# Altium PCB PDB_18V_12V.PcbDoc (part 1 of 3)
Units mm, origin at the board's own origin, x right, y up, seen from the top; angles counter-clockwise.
Board outline 185 x 160 mm, 4 copper layers (Top Layer, Int1 (GND), Int2 (GND), Bottom Layer), stack 1.636 mm thick; 209 components, 100 nets, 653 pads, 1413 vias.
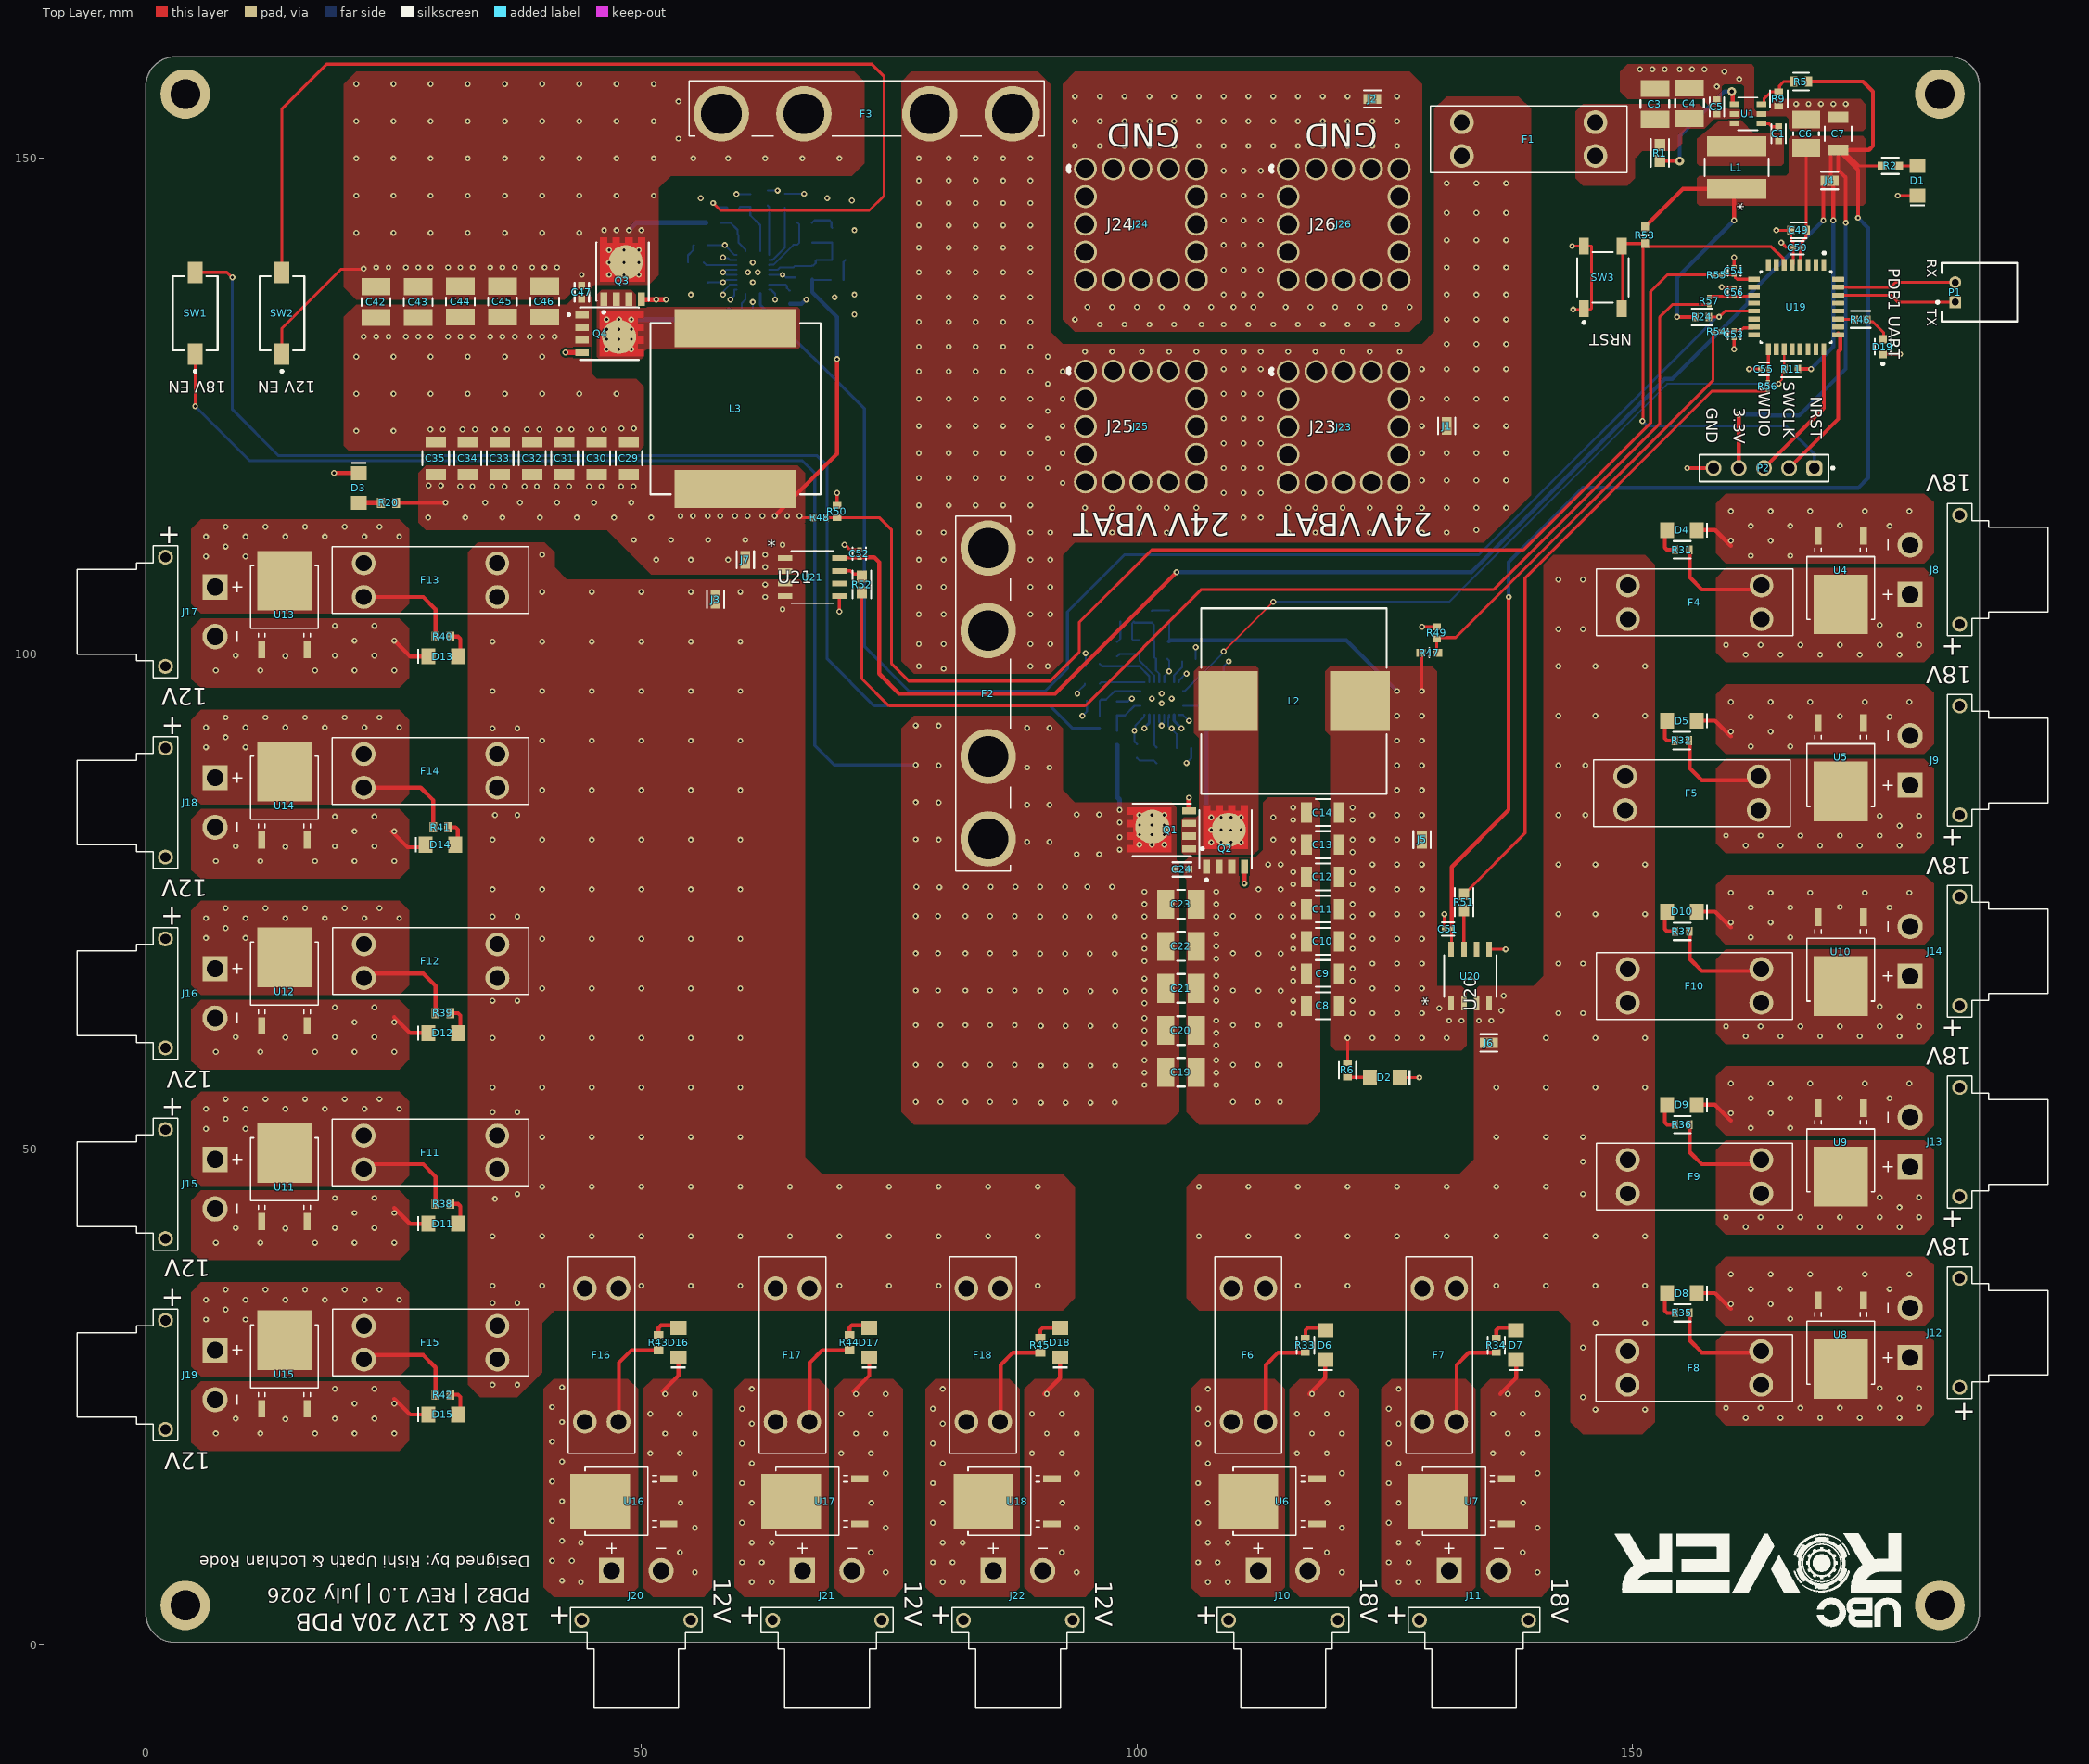
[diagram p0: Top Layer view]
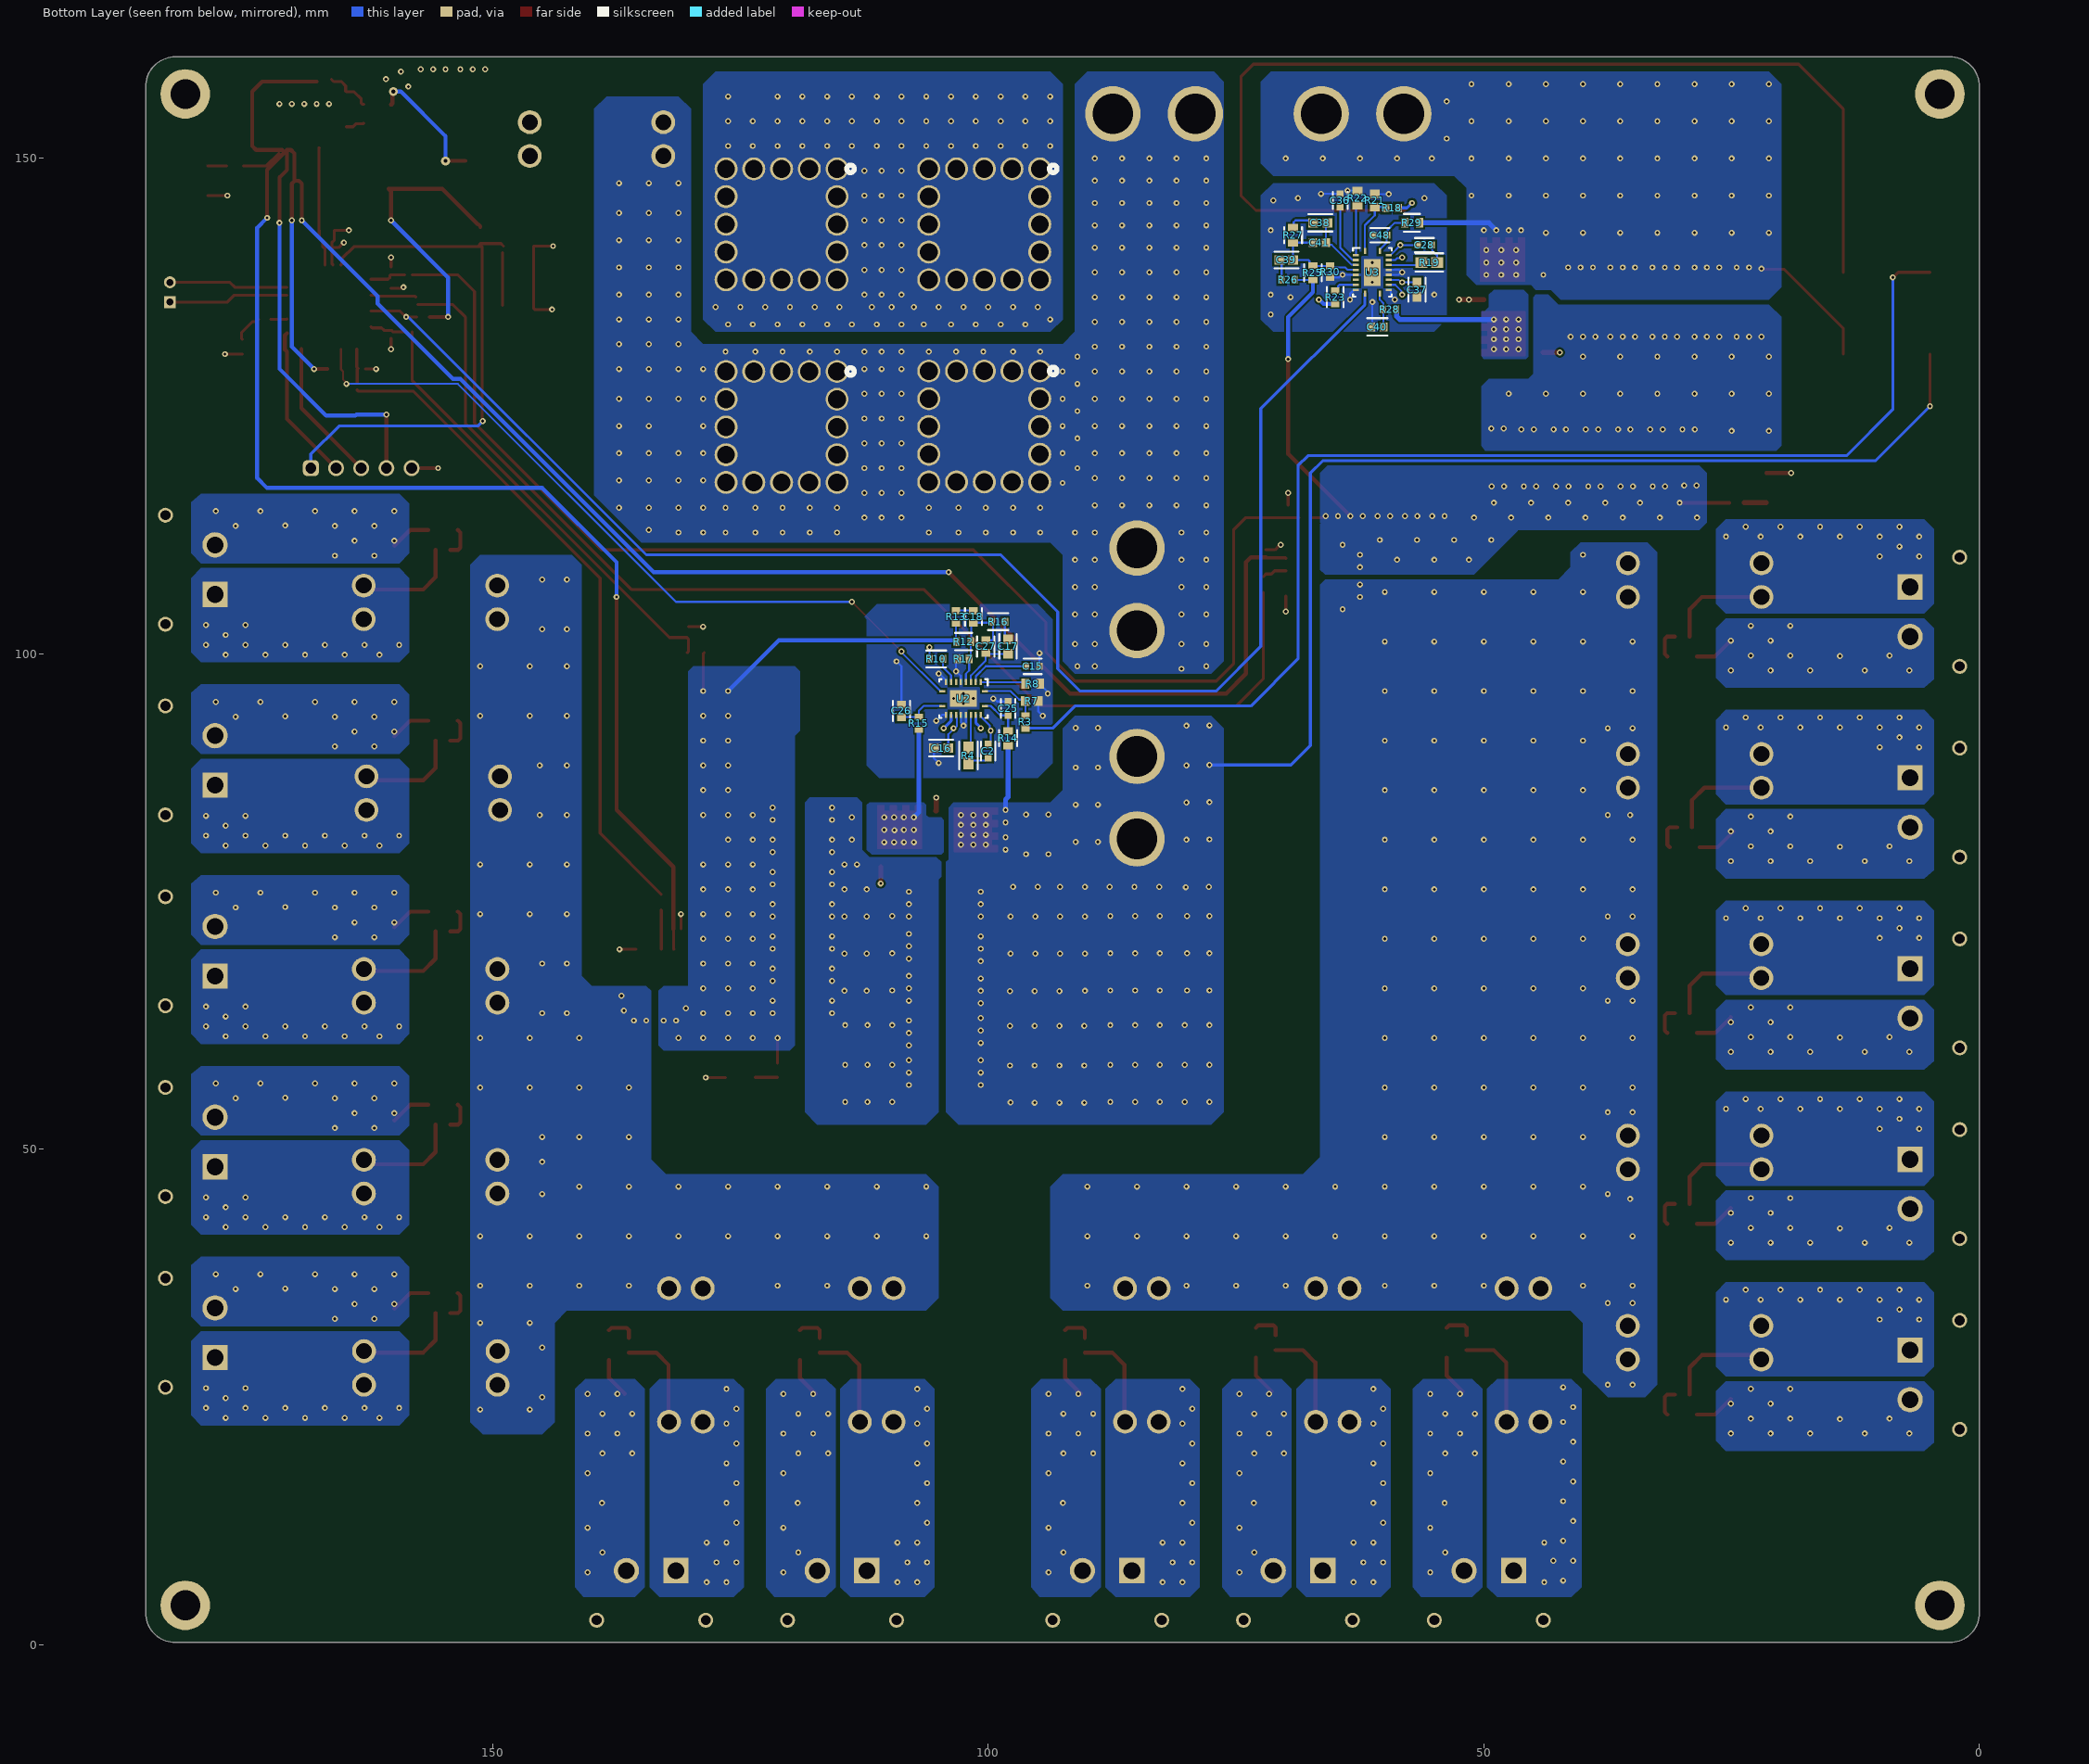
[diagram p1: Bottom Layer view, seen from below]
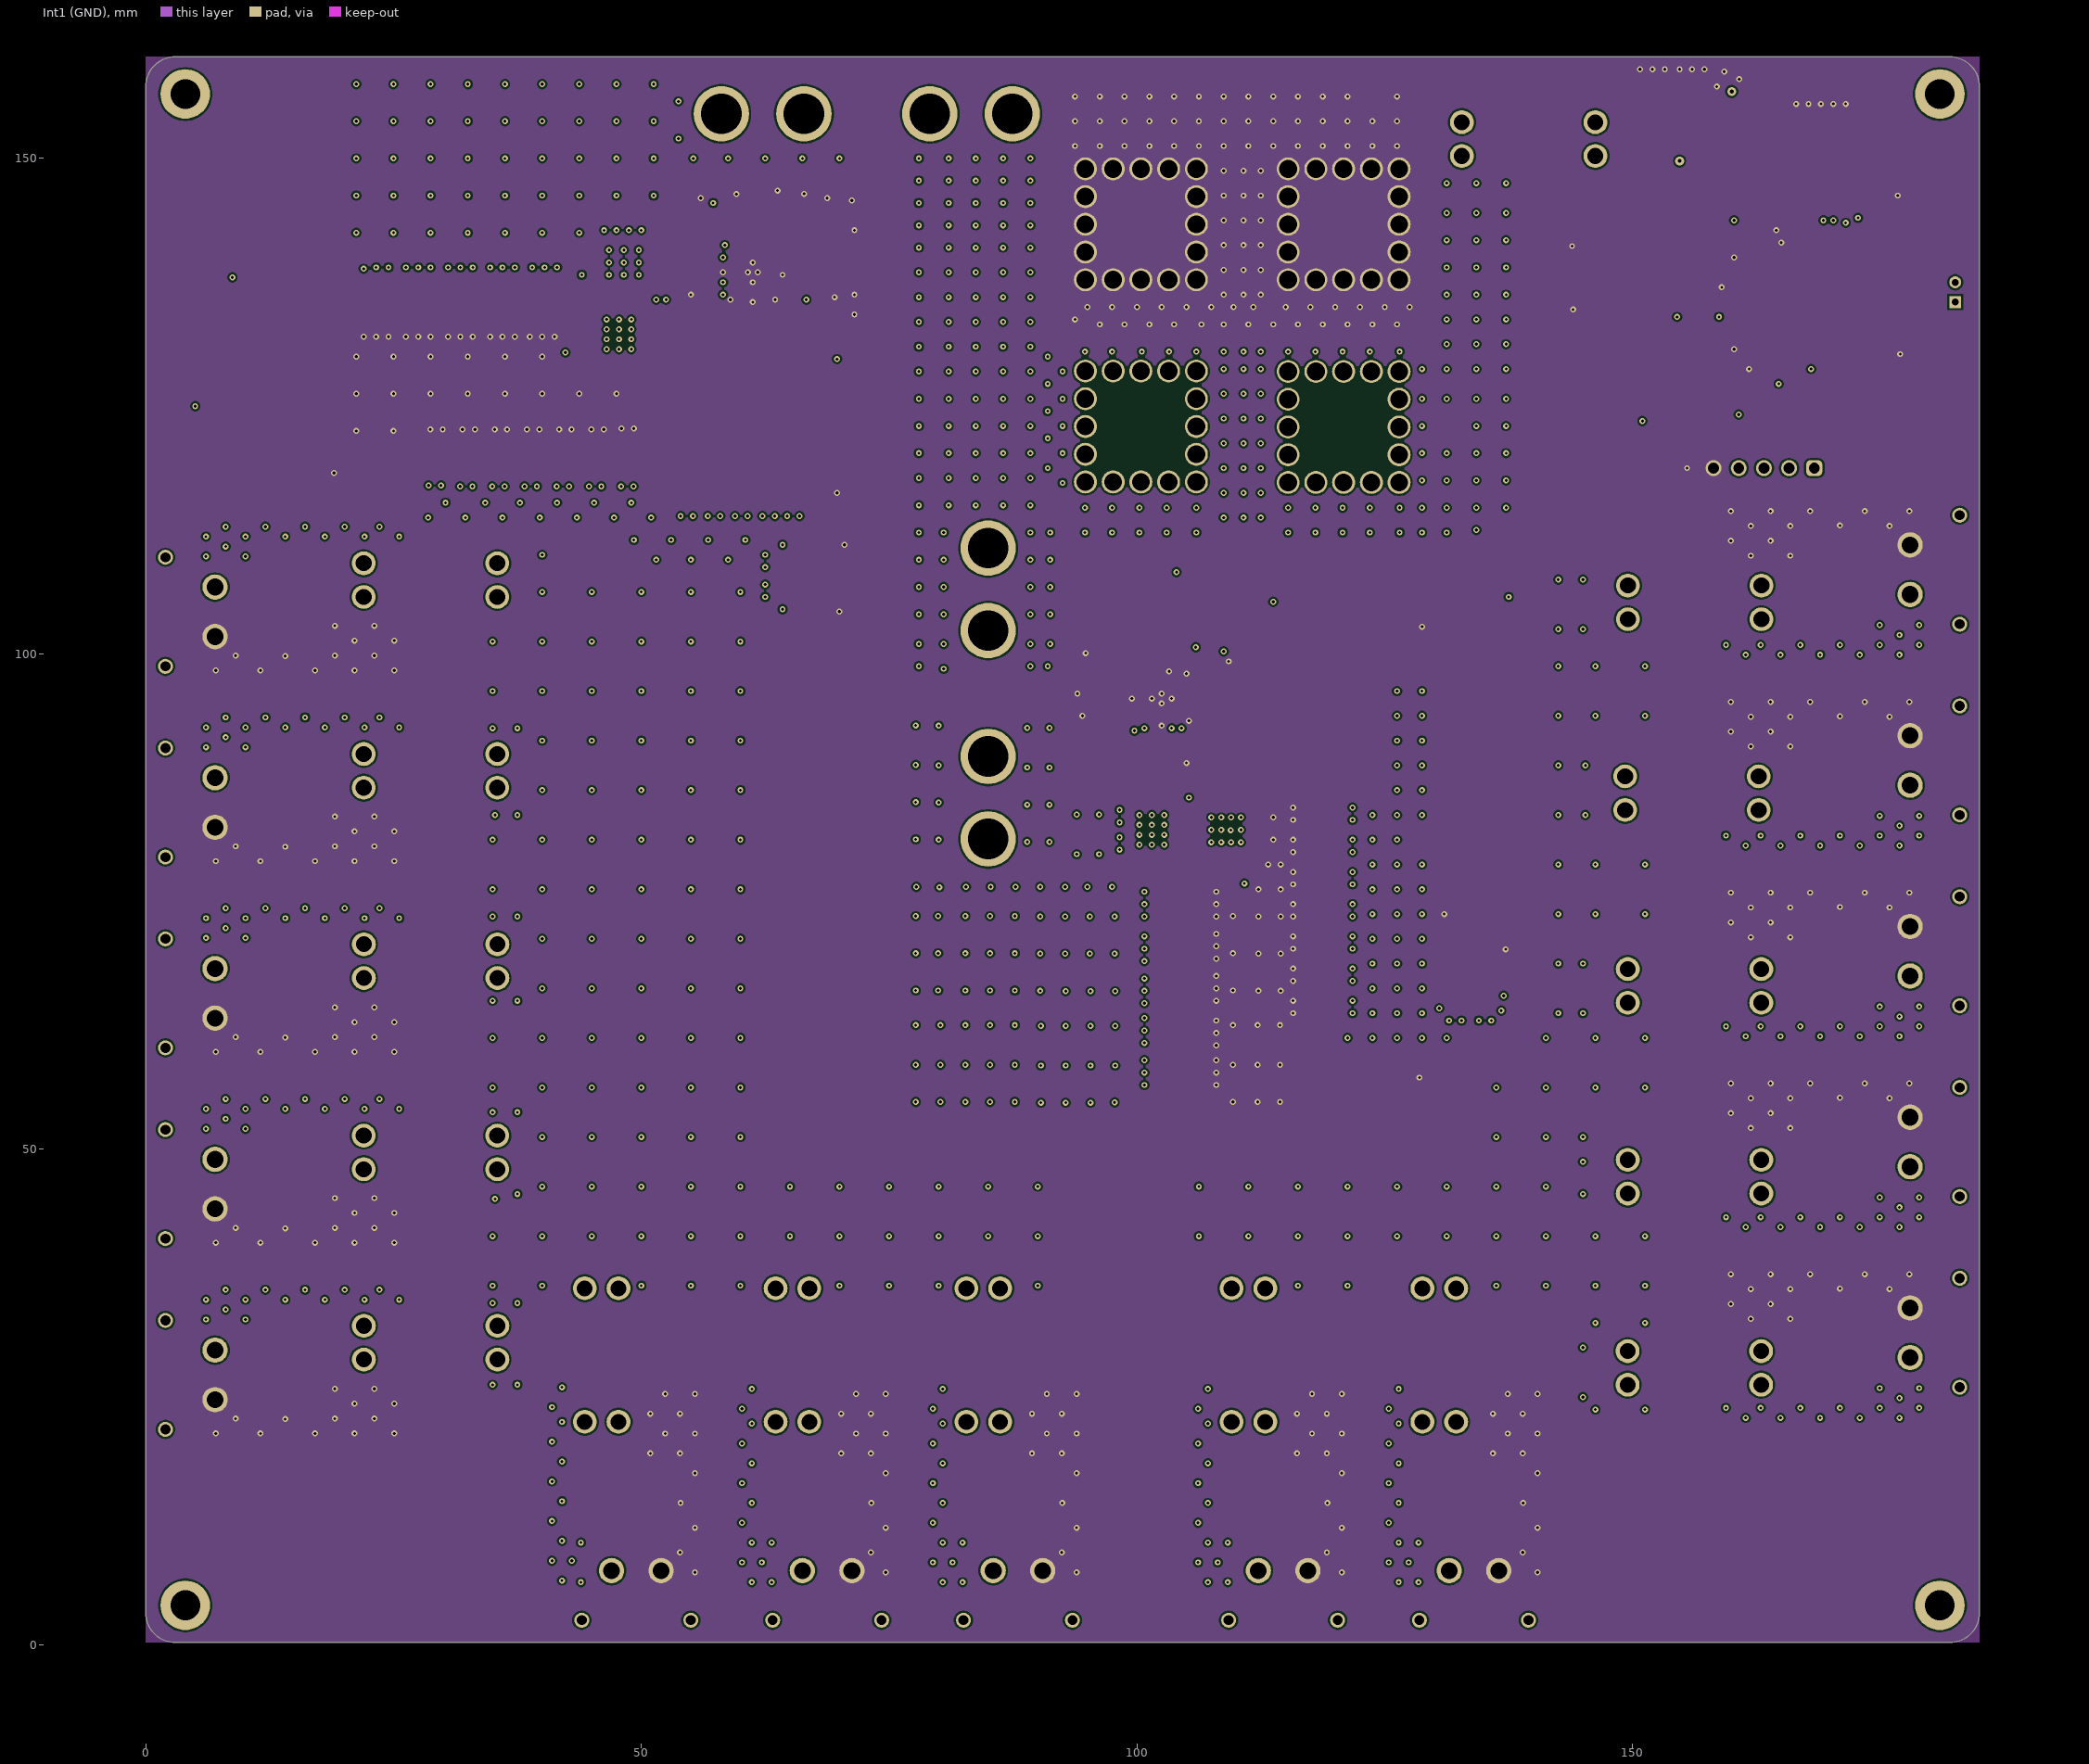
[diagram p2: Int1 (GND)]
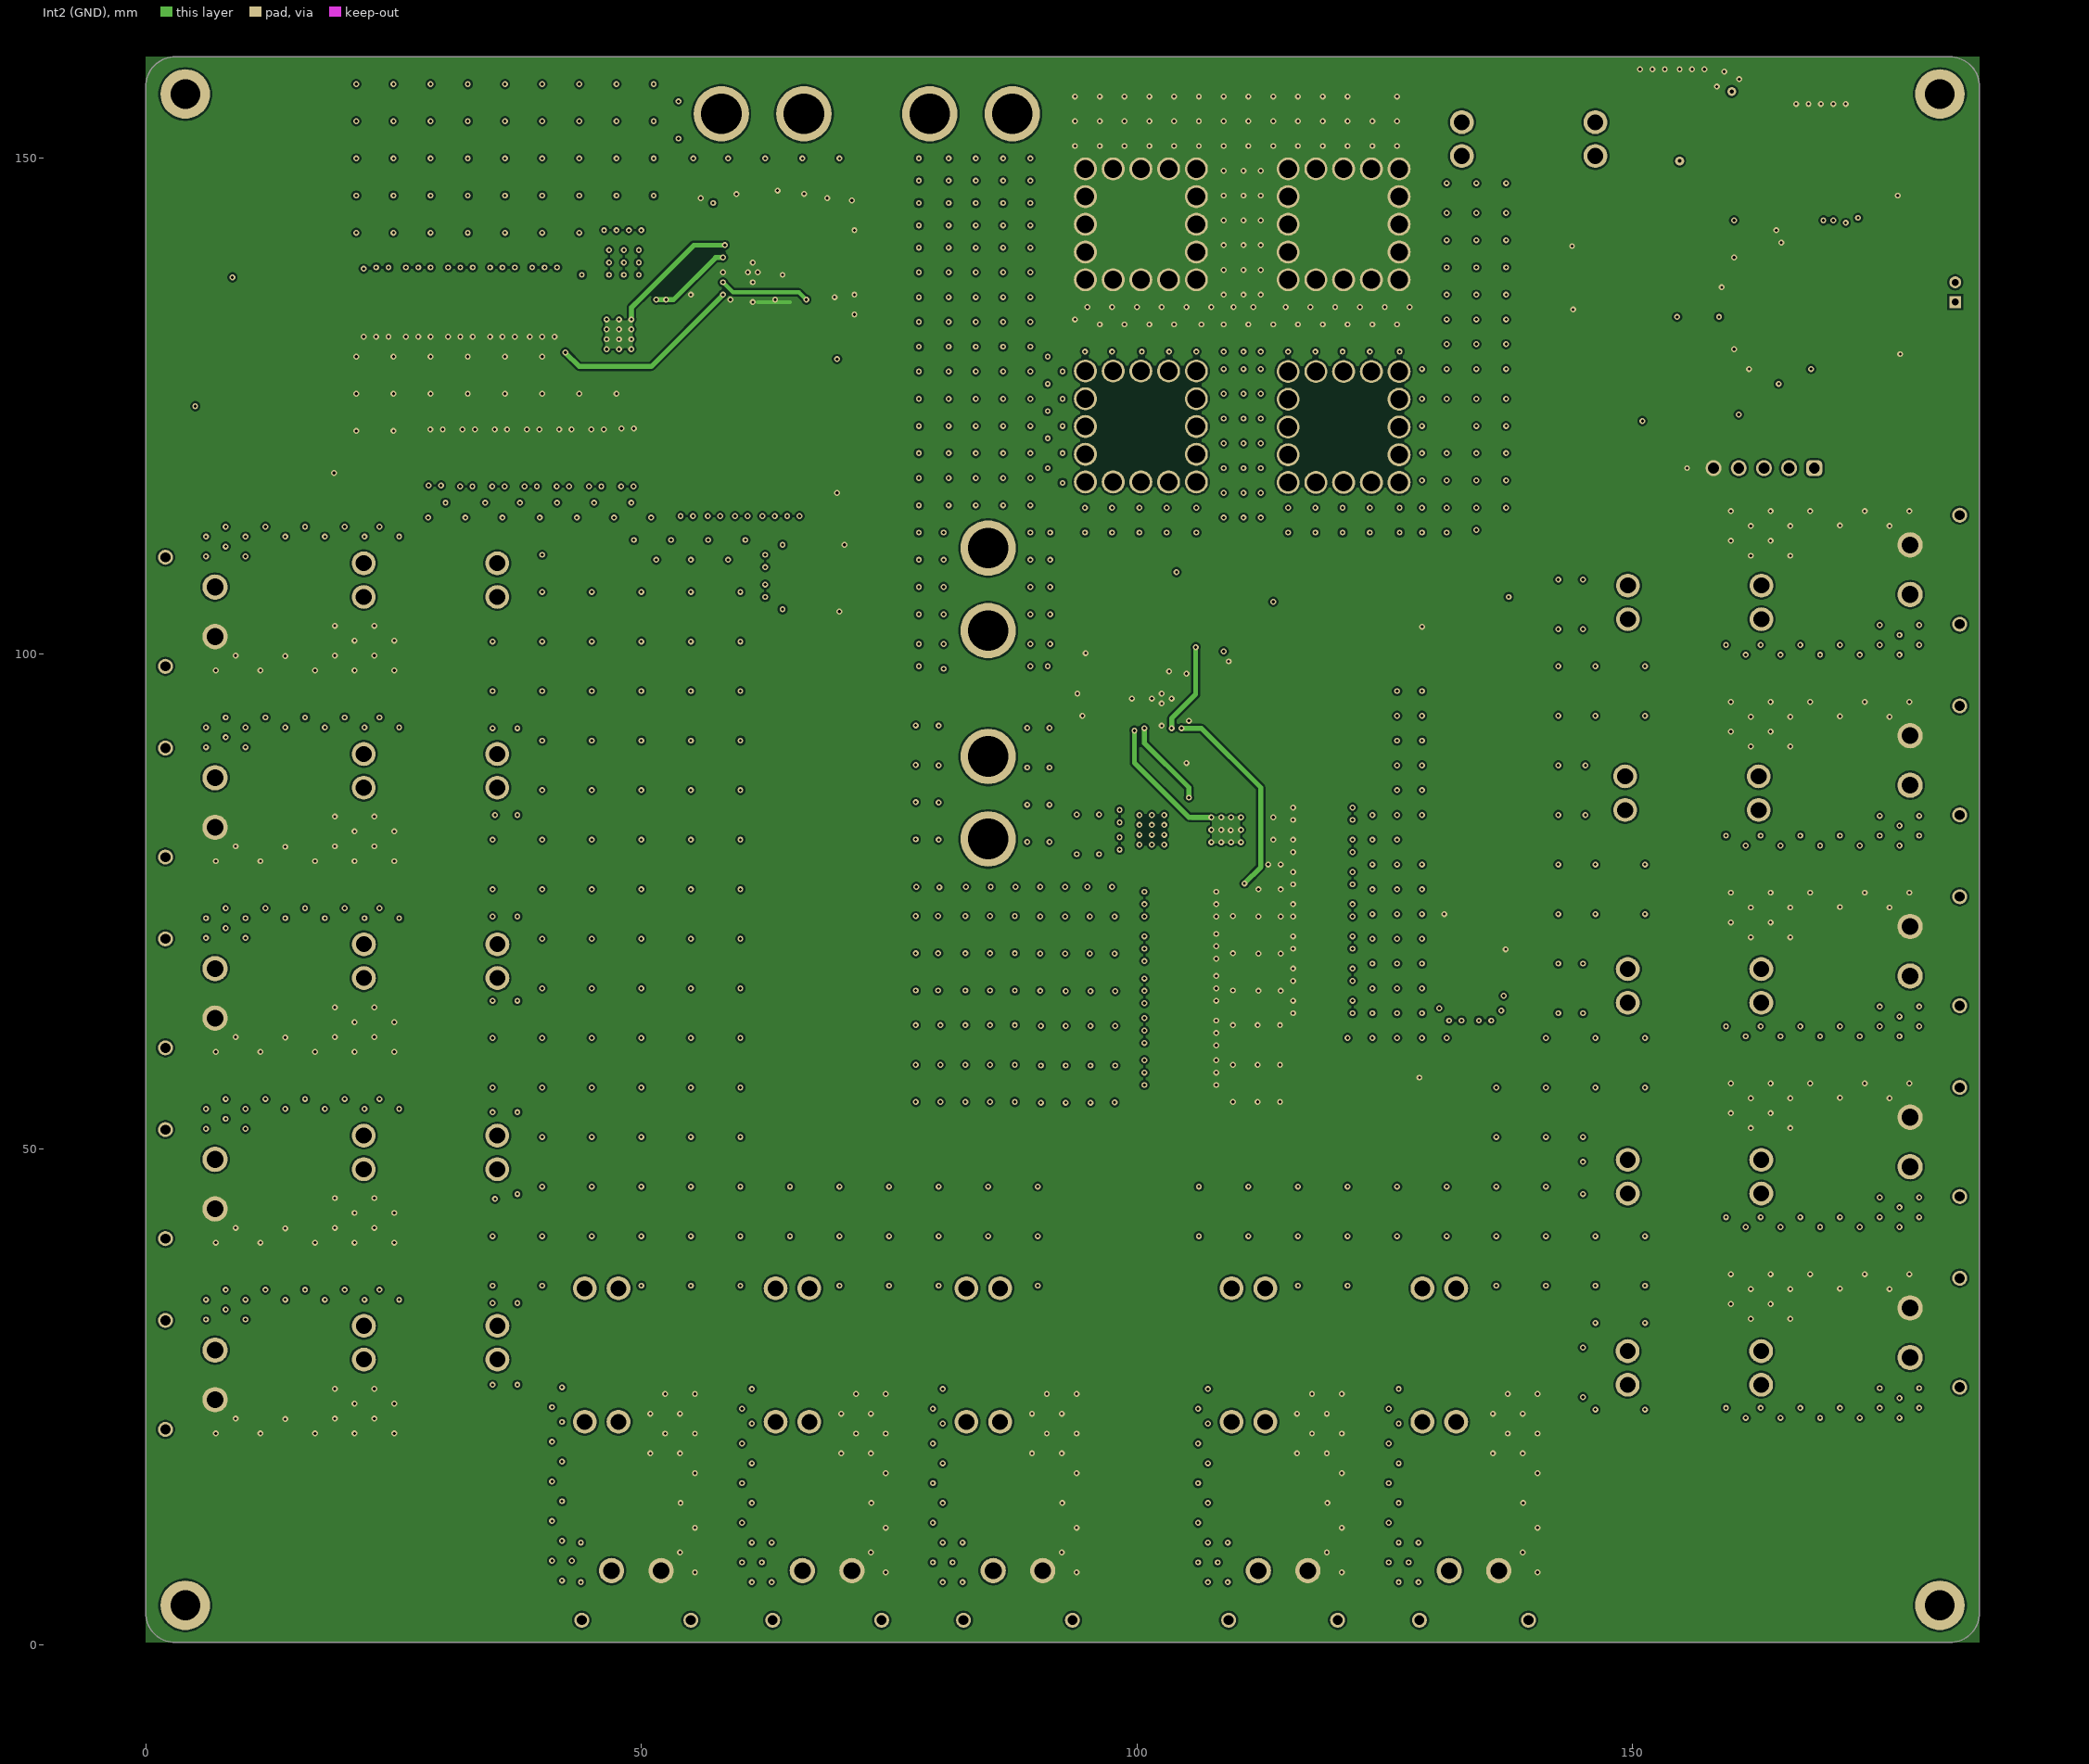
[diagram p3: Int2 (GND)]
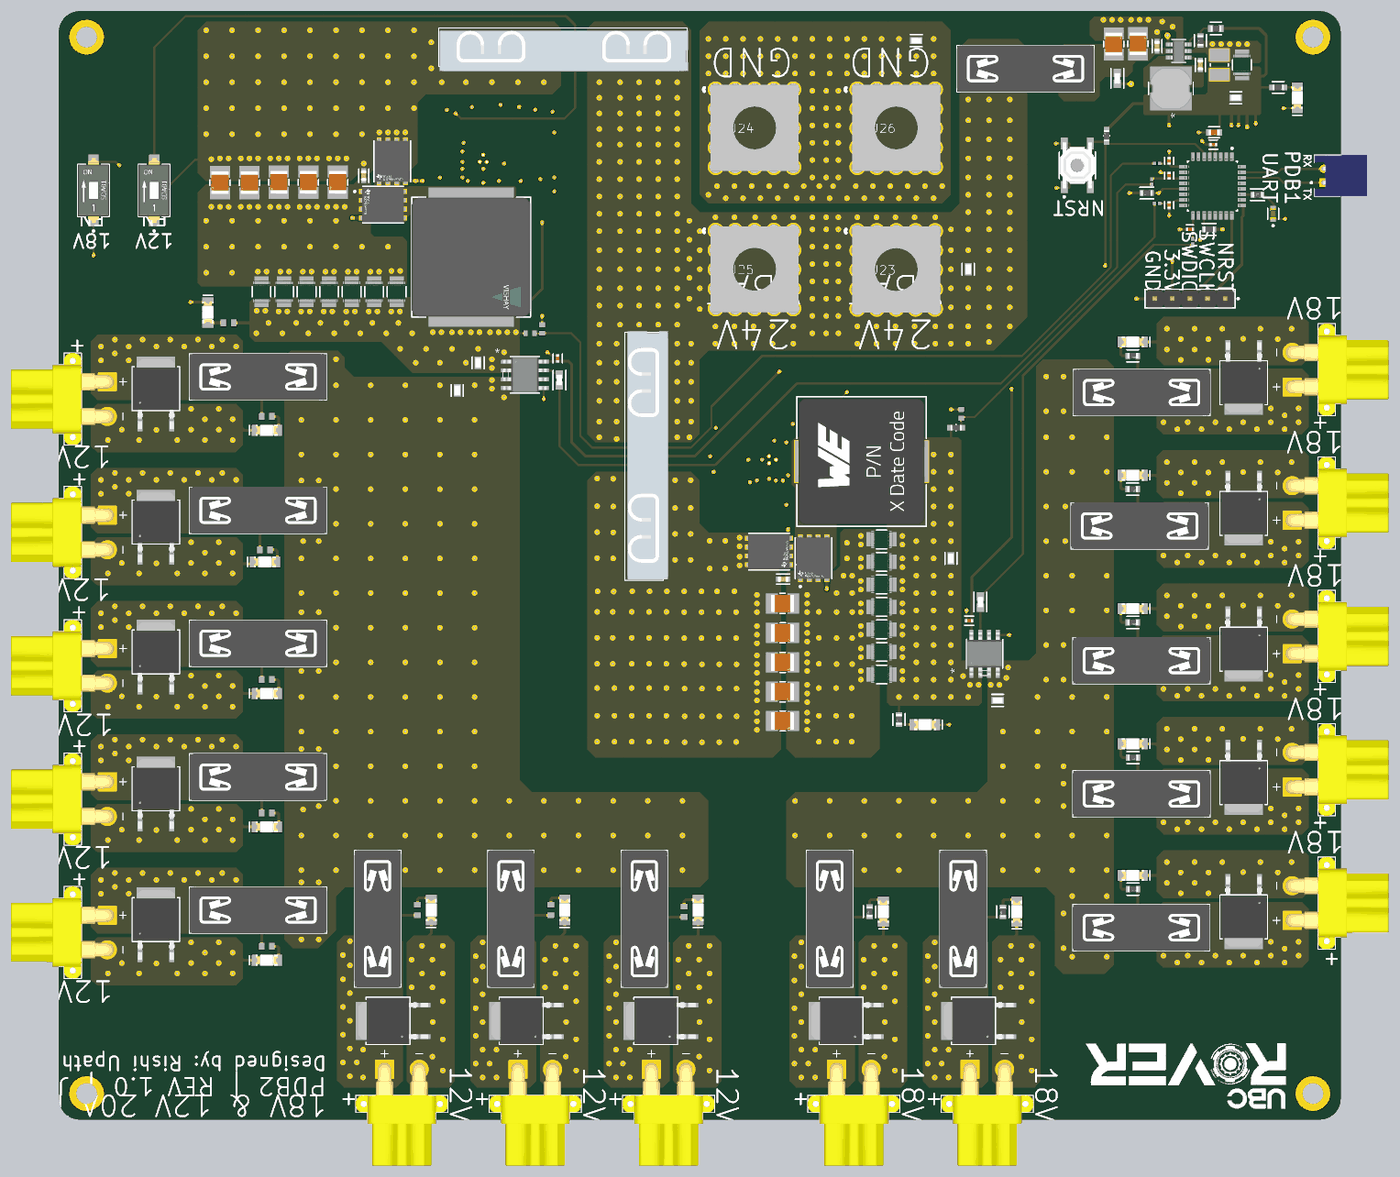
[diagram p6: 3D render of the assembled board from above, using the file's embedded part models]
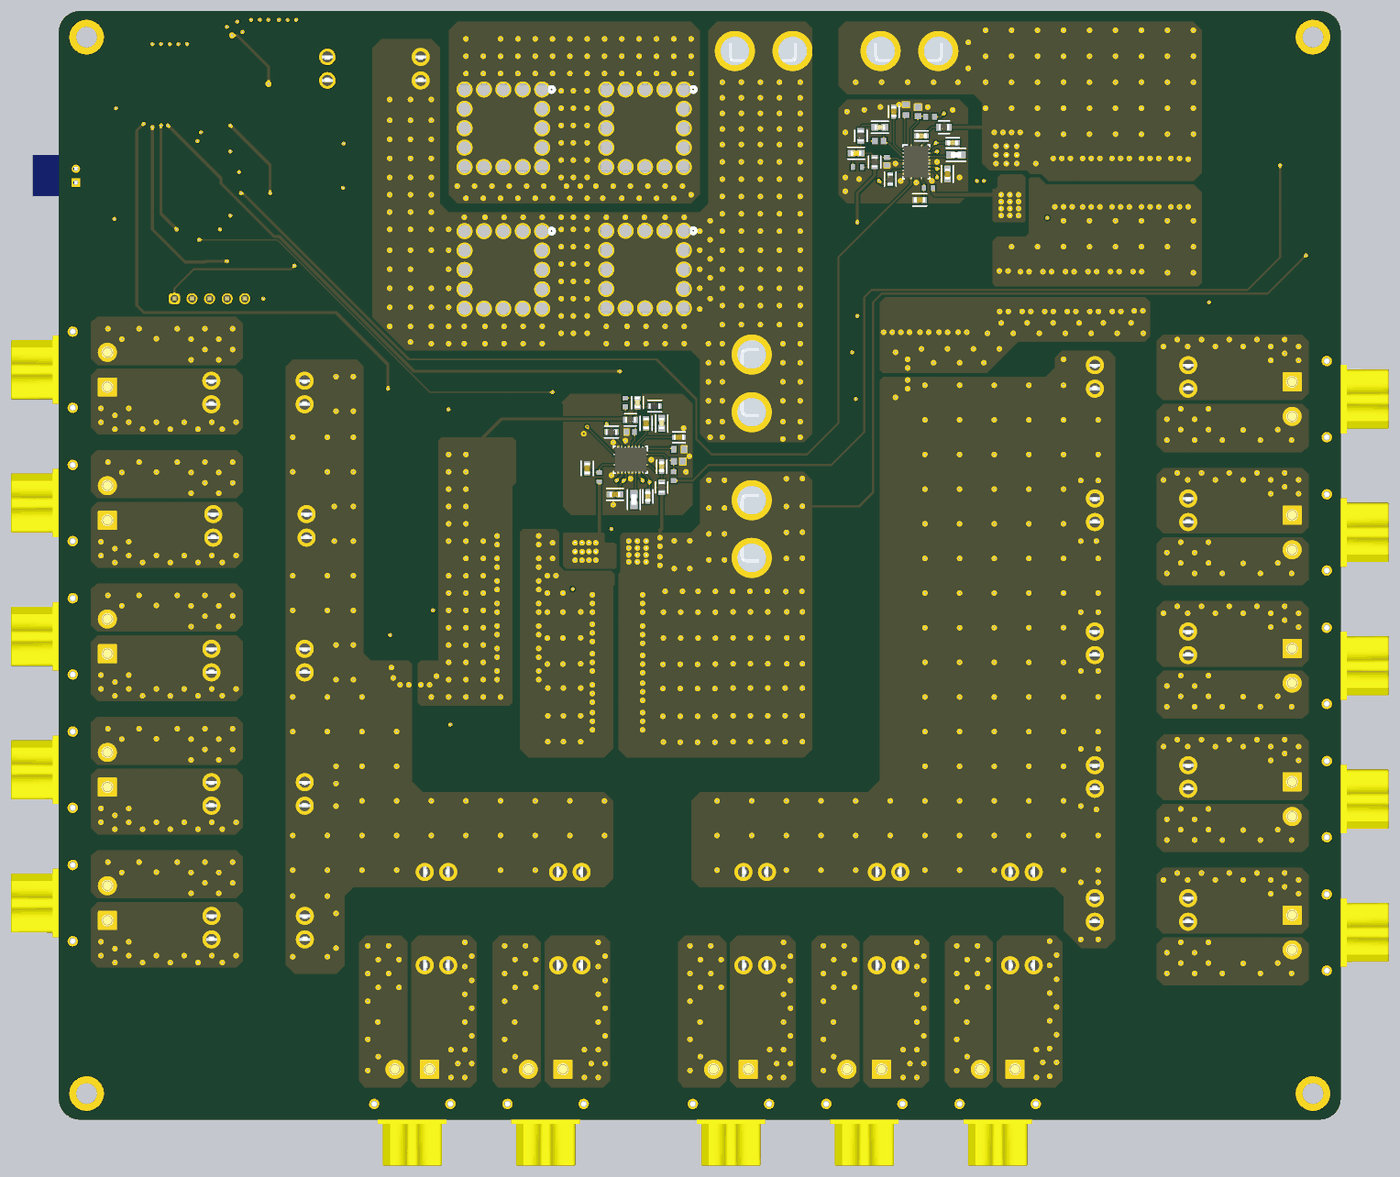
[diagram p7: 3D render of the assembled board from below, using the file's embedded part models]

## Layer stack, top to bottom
Top Solder: solder mask 0.0254, SM-001, Dk 4
Top Layer: signal copper 0.07
Dielectric 1: prepreg 0.203, PP-022, Dk 4.5
Int1 (GND): signal copper 0.03
Dielectric 3: core 1.03, Core-039, Dk 4.8
Int2 (GND): signal copper 0.03
Dielectric 5: prepreg 0.203, PP-022, Dk 4.5
Bottom Layer: signal copper 0.07
Bottom Solder: solder mask 0.0254, SM-001, Dk 4

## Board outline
3,0.25 cw(c3,3.25) 0,3.25 0,157.25 cw(c3,157.25) 3,160.25 182,160.25 cw(c182,157.25) 185,157.25 185,3.25 cw(c182,3.25) 182,0.25

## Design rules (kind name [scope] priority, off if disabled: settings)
Clearance [All] p1: gap=0.2 ignorepadtopadclearanceinfootprint=FALSE
DiffPairsRouting DiffPairsRouting_CAN [InDifferentialPair('CAN')] p1: maxlimit=0.254 minlimit=0.203 mostfreqgap=0.254 toplayer_maxgap=0.203 toplayer_prefgap=0.203 toplayer_minwidth=0.097 toplayer_maxwidth=0.097 toplayer_prefwidth=0.097 midlayer1_minwidth=0.381 midlayer1_maxwidth=0.381 midlayer1_prefwidth=0.381 midlayer2_minwidth=0.381 midlayer2_maxwidth=0.381 midlayer2_prefwidth=0.381 bottomlayer_maxgap=0.203 bottomlayer_prefgap=0.203 bottomlayer_minwidth=0.097 bottomlayer_maxwidth=0.097 bottomlayer_prefwidth=0.097 impedanceprofiledriven=TRUE impedanceprofileid={7FC673FF-01E3-40F9-A78E-6FFD32FF9D5F} maxuncoupledlength=12.7
DiffPairsRouting DiffPairsRouting_USB [InDifferentialPair('USB_D')] p2: maxlimit=0.254 minlimit=0.127 mostfreqgap=0.254 toplayer_maxgap=0.127 toplayer_prefgap=0.127 toplayer_minwidth=0.148 toplayer_maxwidth=0.148 toplayer_prefwidth=0.148 midlayer1_minwidth=0.381 midlayer1_maxwidth=0.381 midlayer1_prefwidth=0.381 midlayer2_minwidth=0.381 midlayer2_maxwidth=0.381 midlayer2_prefwidth=0.381 bottomlayer_maxgap=0.127 bottomlayer_prefgap=0.127 bottomlayer_minwidth=0.148 bottomlayer_maxwidth=0.148 bottomlayer_prefwidth=0.148 impedanceprofiledriven=TRUE impedanceprofileid={548AC05E-11D8-4320-9B4C-721629B8BD8F} maxuncoupledlength=12.7
HoleSize [All] p1: absolutevalues=TRUE maxlimit=6.3 minlimit=0.025 maxpercent=80.000 minpercent=20.000
HoleToHoleClearance [All] p1: gap=0.2 allowstackedmicrovias=TRUE
PlaneConnect [All] p1: planeconnectstyle=Direct reliefexpansion=0.508 reliefentries=4 reliefconductorwidth=0.254 reliefairgap=0.254
PolygonConnect [All] p1: connectstyle=Direct reliefconductorwidth=0.254 reliefentries=4 polygonreliefangle="90 Angle" airgapwidth=0.254
RoutingVias [All] p1: holewidth=0.3 width=0.7 viastyle="Through Hole" minholewidth=0.25 minwidth=0.55 maxholewidth=0.4 maxwidth=0.9
SolderMaskExpansion [All] p1: expansion=0.102 istentingtop=FALSE
SupplyNets "Schematic Supply Nets_46" [InNet('18V_S')] p1: voltage=0.000
SupplyNets "Schematic Supply Nets_45" [InNet('18V')] p2: voltage=0.000
SupplyNets "Schematic Supply Nets_44" [InNet('12V_Spare1')] p3: voltage=0.000
SupplyNets "Schematic Supply Nets_43" [InNet('12V_RoverLab1')] p4: voltage=0.000
SupplyNets "Schematic Supply Nets_42" [InNet('12V_PTZ')] p5: voltage=0.000
SupplyNets "Schematic Supply Nets_41" [InNet('18V_JETSON')] p6: voltage=0.000
SupplyNets "Schematic Supply Nets_40" [InNet('12V_Fans')] p7: voltage=0.000
SupplyNets "Schematic Supply Nets_39" [InNet('12V_S')] p8: voltage=0.000
SupplyNets "Schematic Supply Nets_38" [InNet('12V_USB_HUB')] p9: voltage=0.000
SupplyNets "Schematic Supply Nets_37" [InNet('24V_BUCK12')] p10: voltage=0.000
SupplyNets "Schematic Supply Nets_36" [InNet('18V_Spare3')] p11: voltage=0.000
SupplyNets "Schematic Supply Nets_35" [InNet('12V')] p12: voltage=0.000
SupplyNets "Schematic Supply Nets_34" [InNet('18V_Spare5')] p13: voltage=0.000
SupplyNets "Schematic Supply Nets_33" [InNet('12V_RoverLab2')] p14: voltage=0.000
SupplyNets "Schematic Supply Nets_32" [InNet('24V_BUCK18')] p15: voltage=0.000
SupplyNets "Schematic Supply Nets_17" [InNet('18V_Spare1')] p16: voltage=0.000
SupplyNets "Schematic Supply Nets_6" [InNet('18V_Spare4')] p17: voltage=0.000
SupplyNets "Schematic Supply Nets_5" [InNet('18V_NUC')] p18: voltage=0.000
SupplyNets "Schematic Supply Nets_3" [InNet('12V_Spare2')] p19: voltage=0.000
SupplyNets "Schematic Supply Nets_2" [InNet('18V_Spare2')] p20: voltage=0.000
SupplyNets "Schematic Supply Nets" [InNet('12V_Spare3')] p21: voltage=0.000
SupplyNets "Schematic Supply Nets_30" [InNet('24V')] p22: voltage=0.000
SupplyNets "Schematic Supply Nets_13" [InNet('24V_BUCK')] p23: voltage=0.000
SupplyNets "Schematic Supply Nets_4" [InNet('3.3V')] p24: voltage=0.000
SupplyNets "Schematic Supply Nets_1" [InNet('GND')] p25: voltage=0.000
UnRoutedNet [All] p1: checkbadconnections=TRUE
Width Width_RF [InNet('RF')] p1: maxlimit=0.348 minlimit=0.254 preferedwidth=0.348 toplayer_minwidth=0.348 bottomlayer_minwidth=0.348 impedanceprofiledriven=TRUE minimp=50.000000 maximp=50.000000 favimp=50.000000
Width Width_All [All] p2: maxlimit=1 minlimit=0.09 preferedwidth=0.3 midlayer1_minwidth=0.254 midlayer1_prefwidth=0.254 midlayer2_minwidth=0.254 midlayer2_prefwidth=0.254 minimp=50.000000 maximp=50.000000 favimp=50.000000
25 further rules are at their usual default settings.

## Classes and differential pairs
component class PDB_18V_12V_Power: C1 C2 C3 C4 C5 C6 C7 C8 C9 C10 C11 C12 C13 C14 C15 C16 C17 C18 C19 C20 C21 C22 C23 C24 C25 C26 C27 C28 C29 C30 C31 C32 C33 C34 C35 C36 C37 C38 C39 C40 C41 C42 C43 C44 C45 C46 C47 C48 D1 D2 D3 F1 F2 F3 J1 J2 J3 J4 J5 J6 J7 L1 L2 L3 Q1 Q2 Q3 Q4 R1 R2 R3 R4 R5 R6 R7 R8 R9 R10 R11 R12 R13 R14 R15 R16 R17 R18 R19 R20 R21 R22 R23 R24 R25 R26 R27 R28 R29 R30 SW1 SW2 U1 U2 U3
component class PDB_18V_12V_MCU_Peripherals: C49 C50 C51 C52 C53 C54 C55 C56 D19 P1 P2 R46 R47 R48 R49 R50 R51 R52 R53 R54 R55 R56 R57 SW3 U19 U20 U21
component class PDB_18V_12V_Connectors: D4 D5 D6 D7 D8 D9 D10 D11 D12 D13 D14 D15 D16 D17 D18 F4 F5 F6 F7 F8 F9 F10 F11 F12 F13 F14 F15 F16 F17 F18 J8 J9 J10 J11 J12 J13 J14 J15 J16 J17 J18 J19 J20 J21 J22 J23 J24 J25 J26 R31 R32 R33 R34 R35 R36 R37 R38 R39 R40 R41 R42 R43 R44 R45 U4 U5 U6 U7 U8 U9 U10 U11 U12 U13 U14 U15 U16 U17 U18

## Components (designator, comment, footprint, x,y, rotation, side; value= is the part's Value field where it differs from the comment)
C1 "CGA3E3X8R1H104K080AB" FP-CGA3E-0_3-0_1-MFG 164.75,152.5 r270 top value=100nF
C2 "CGA3E3X8R1H104K080AB" FP-CGA3E-0_3-0_1-MFG 100,90.2 r90 bottom value=100nF
C3 "12105C475KAT2A" FP-1210-L_3_3_0_4-W_2_5_0-IPC_A 152.25,155.5 r90 top value=4.7uF
C4 "12105C475KAT2A" FP-1210-L_3_3_0_4-W_2_5_0-IPC_A 155.75,155.55 r90 top value=4.7uF
C5 "CGA3E3X8R1H104K080AB" FP-CGA3E-0_3-0_1-MFG 158.5,155.2 r270 top value=100nF
C6 "UMK325BJ106MM-T" TAYO-C1210-2_M 167.5,152.5 r270 top value=10µF
C7 "GRM32ER61E226KE15L" FP-GRM32-MFG 170.75,152.5 r270 top value=22µF
C8 "GRM32ER61E226KE15L" FP-GRM32-MFG 118.75,64.5 r0 top value=22µF
C9 "GRM32ER61E226KE15L" FP-GRM32-MFG 118.75,67.75 r0 top value=22µF
C10 "GRM32ER61E226KE15L" FP-GRM32-MFG 118.75,71 r0 top value=22µF
C11 "GRM32ER61E226KE15L" FP-GRM32-MFG 118.75,74.25 r0 top value=22µF
C12 "GRM32ER61E226KE15L" FP-GRM32-MFG 118.75,77.5 r0 top value=22µF
C13 "GRM32ER61E226KE15L" FP-GRM32-MFG 118.75,80.75 r0 top value=22µF
C14 "GRM32ER61E226KE15L" FP-GRM32-MFG 118.75,84 r0 top value=22µF
C15 "GCJ188R71C393KA01J" FP-GCJ188-0_2-MFG 95.5,98.75 r180 bottom value=39nF
C16 "GRM188R6YA225KA12D" FP-GRM188-0_1-e0_2_0_5-IPC_B 104.75,90.5 r180 bottom value=2.2µF
C17 "C0603C472J5RACTU" FP-C0603C-CF-IPC_B 98,100.75 r90 bottom value=4n7F
C18 "C0603C821K5RACTU" FP-C0603C-CF-MFG 101.5,103.75 r90 bottom value=820pF
C19 "12105C475KAT2A" FP-1210-L_3_3_0_4-W_2_5_0-IPC_A 104.45,57.785 r0 top value=4.7uF
C20 "12105C475KAT2A" FP-1210-L_3_3_0_4-W_2_5_0-IPC_A 104.45,62 r0 top value=4.7uF
C21 "12105C475KAT2A" FP-1210-L_3_3_0_4-W_2_5_0-IPC_A 104.45,66.25 r0 top value=4.7uF
C22 "12105C475KAT2A" FP-1210-L_3_3_0_4-W_2_5_0-IPC_A 104.45,70.5 r0 top value=4.7uF
C23 "12105C475KAT2A" FP-1210-L_3_3_0_4-W_2_5_0-IPC_A 104.45,74.75 r0 top value=4.7uF
C24 "CGA3E3X8R1H104K080AB" FP-CGA3E-0_3-0_1-MFG 104.55,78.25 r0 top value=100nF
C25 "CGA3E3X8R1H104K080AB" FP-CGA3E-0_3-0_1-MFG 98,94.5 r90 bottom value=100nF
C26 "06035A150JAT2A" FP-0603-L_1_6_0_15-W_0_81-IPC_C 108.75,94.25 r90 bottom value=15pF
C27 "06035C221KAT2A" FP-0603-L_1_6_0_15-W_0_81-IPC_C 100.25,100.75 r90 bottom value=220pF
C28 "CGA3E3X8R1H104K080AB" FP-CGA3E-0_3-0_1-MFG 56,141.25 r0 bottom value=100nF
C29 "GRM32ER61E226KE15L" FP-GRM32-MFG 48.75,119.75 r270 top value=22µF
C30 "GRM32ER61E226KE15L" FP-GRM32-MFG 45.5,119.75 r270 top value=22µF
C31 "GRM32ER61E226KE15L" FP-GRM32-MFG 42.25,119.75 r270 top value=22µF
C32 "GRM32ER61E226KE15L" FP-GRM32-MFG 39,119.75 r270 top value=22µF
C33 "GRM32ER61E226KE15L" FP-GRM32-MFG 35.75,119.75 r270 top value=22µF
C34 "GRM32ER61E226KE15L" FP-GRM32-MFG 32.5,119.75 r270 top value=22µF
C35 "GRM32ER61E226KE15L" FP-GRM32-MFG 29.25,119.75 r270 top value=22µF
C36 "GCM188L81H823KA57J" FP-GCM188-0_1-MFG 64.5,145.75 r270 bottom value=82nF
C37 "GRM188R6YA225KA12D" FP-GRM188-0_1-e0_2_0_5-IPC_B 56.75,136.75 r90 bottom value=2.2µF
C38 "C0603C472J5RACTU" FP-C0603C-CF-IPC_B 66.5,143.5 r0 bottom value=4n7F
C39 "CC0603KRX7R9BB122" FP-CC0603-DA-IPC_B 69.927,139.75 r0 bottom value=1n2F
C40 "06035A150JAT2A" FP-0603-L_1_6_0_15-W_0_81-IPC_C 60.75,133 r0 bottom value=15pF
C41 "C0603C151J5GACTU" CAPC1608X90X35LL15T15 66.6,141.5 r0 bottom value=150pF
C42 "12105C475KAT2A" FP-1210-L_3_3_0_4-W_2_5_0-IPC_A 23.25,135.5 r270 top value=4.7uF
C43 "12105C475KAT2A" FP-1210-L_3_3_0_4-W_2_5_0-IPC_A 27.5,135.5 r270 top value=4.7uF
C44 "12105C475KAT2A" FP-1210-L_3_3_0_4-W_2_5_0-IPC_A 31.75,135.55 r270 top value=4.7uF
C45 "12105C475KAT2A" FP-1210-L_3_3_0_4-W_2_5_0-IPC_A 36,135.55 r270 top value=4.7uF
C46 "12105C475KAT2A" FP-1210-L_3_3_0_4-W_2_5_0-IPC_A 40.25,135.55 r270 top value=4.7uF
C47 "CGA3E3X8R1H104K080AB" FP-CGA3E-0_3-0_1-MFG 44,136.5 r270 top value=100nF
C48 "CGA3E3X8R1H104K080AB" FP-CGA3E-0_3-0_1-MFG 60.5,142.25 r0 bottom value=100nF
C49 "GRM188R61E475KE11D" FP-GRM188-0_15-MFG 166.75,142.75 r0 top value=4.7µF
C50 "CL05B104KA5NNNC" FP-CL830-IPC_C 166.629,141 r0 top value=100nF
C51 "CL05B104KA5NNNC" FP-CL830-IPC_C 131.379,72.25 r0 top value=100nF
C52 "CL05B104KA5NNNC" FP-CL830-IPC_C 72,110.129 r270 top value=100nF
C53 "GRM1555C1H102JA01D" FP-GRM155-0_05-MFG 160.25,132.25 r90 top value=1nF
C54 "GRM1555C1H102JA01D" FP-GRM155-0_05-MFG 160.25,138.65 r270 top value=1nF
C55 "GRM1555C1H102JA01D" FP-GRM155-0_05-MFG 163.25,128.75 r0 top value=1nF
C56 "GRM1555C1H102JA01D" FP-GRM155-0_05-MFG 160.25,136.5 r270 top value=1nF
D1 "150120VS75000" WL-SMCW_1206_150120xx75000 178.75,147.75 r90 top
D2 "150120VS75000" WL-SMCW_1206_150120xx75000 125,57.25 r180 top
D3 "150120VS75000" WL-SMCW_1206_150120xx75000 21.5,116.75 r270 top
D4 "150120VS75000" WL-SMCW_1206_150120xx75000 155,112.5 r180 top
D5 "150120VS75000" WL-SMCW_1206_150120xx75000 155,93.25 r180 top
D6 "150120VS75000" WL-SMCW_1206_150120xx75000 119,30.25 r90 top
D7 "150120VS75000" WL-SMCW_1206_150120xx75000 138.25,30.25 r90 top
D8 "150120VS75000" WL-SMCW_1206_150120xx75000 155,35.5 r180 top
D9 "150120VS75000" WL-SMCW_1206_150120xx75000 155,54.5 r180 top
D10 "150120VS75000" WL-SMCW_1206_150120xx75000 155,74 r180 top
D11 "150120VS75000" WL-SMCW_1206_150120xx75000 30,42.5 r0 top
D12 "150120VS75000" WL-SMCW_1206_150120xx75000 30,61.75 r0 top
D13 "150120VS75000" WL-SMCW_1206_150120xx75000 30,99.75 r0 top
D14 "150120VS75000" WL-SMCW_1206_150120xx75000 29.75,80.75 r0 top
D15 "150120VS75000" WL-SMCW_1206_150120xx75000 30,23.25 r0 top
D16 "150120VS75000" WL-SMCW_1206_150120xx75000 53.75,30.5 r90 top
D17 "150120VS75000" WL-SMCW_1206_150120xx75000 73,30.5 r90 top
D18 "150120VS75000" WL-SMCW_1206_150120xx75000 92.25,30.5 r90 top
D19 "LTST-C191KGKT" FP-LTST-C191KGKT-MFG 175.25,131 r90 top
F1 "3557-2" FUSE_3557-2 139.515,151.95 r0 top
F2 "3555-2" FUSE_3555-2 85,96 r270 top
F3 "3555-2" FUSE_3555-2 72.75,154.5 r180 top
F4 "3557-2" FUSE_3557-2 156.265,105.2 r0 top
F5 "3557-2" FUSE_3557-2 155.985,85.95 r0 top
F6 "3557-2" FUSE_3557-2 111.25,29.25 r270 top
F7 "3557-2" FUSE_3557-2 130.5,29.25 r270 top
F8 "3557-2" FUSE_3557-2 156.235,27.95 r0 top
F9 "3557-2" FUSE_3557-2 156.25,47.25 r0 top
F10 "3557-2" FUSE_3557-2 156.25,66.5 r0 top
F11 "3557-2" FUSE_3557-2 28.735,49.7 r180 top
F12 "3557-2" FUSE_3557-2 28.75,69 r180 top
F13 "3557-2" FUSE_3557-2 28.735,107.45 r180 top
F14 "3557-2" FUSE_3557-2 28.735,88.2 r180 top
F15 "3557-2" FUSE_3557-2 28.75,30.5 r180 top
F16 "3557-2" FUSE_3557-2 46,29.25 r270 top
F17 "3557-2" FUSE_3557-2 65.25,29.25 r270 top
F18 "3557-2" FUSE_3557-2 84.5,29.25 r270 top
J1 "S2761-46R" FP-S2761-46R-MFG 131.25,123 r90 top
J2 "S2761-46R" FP-S2761-46R-MFG 123.75,156 r0 top
J3 "S2761-46R" FP-S2761-46R-MFG 57.5,105.5 r90 top
J4 "S2761-46R" FP-S2761-46R-MFG 169.87,147.75 r0 top
J5 "S2761-46R" FP-S2761-46R-MFG 128.75,81.25 r90 top
J6 "S2761-46R" FP-S2761-46R-MFG 135.5,60.75 r0 top
J7 "S2761-46R" FP-S2761-46R-MFG 60.5,109.5 r90 top
J8 "XT30PW-F" AMASS_XT30PW-F 183,108.5 r270 top
J9 "XT30PW-F" AMASS_XT30PW-F 183,89.25 r270 top
J10 "XT30PW-F" AMASS_XT30PW-F 114.75,2.5 r180 top
J11 "XT30PW-F" AMASS_XT30PW-F 134,2.5 r180 top
J12 "XT30PW-F" AMASS_XT30PW-F 183,31.5 r270 top
J13 "XT30PW-F" AMASS_XT30PW-F 183,50.75 r270 top
J14 "XT30PW-F" AMASS_XT30PW-F 183,70 r270 top
J15 "XT30PW-F" AMASS_XT30PW-F 2,46.5 r90 top
J16 "XT30PW-F" AMASS_XT30PW-F 2,65.75 r90 top
J17 "XT30PW-F" AMASS_XT30PW-F 2,104.25 r90 top
J18 "XT30PW-F" AMASS_XT30PW-F 2,85 r90 top
J19 "XT30PW-F" AMASS_XT30PW-F 2,27.25 r90 top
J20 "XT30PW-F" AMASS_XT30PW-F 49.5,2.5 r180 top
J21 "XT30PW-F" AMASS_XT30PW-F 68.75,2.5 r180 top
J22 "XT30PW-F" AMASS_XT30PW-F 88,2.5 r180 top
J23 "S93515" CONN16_S93515_WRE 115.25,128.5 r0 top
J24 "S93515" CONN16_S93515_WRE 94.8,148.95 r0 top
J25 "S93515" CONN16_S93515_WRE 94.8,128.55 r0 top
J26 "S93515" CONN16_S93515_WRE 115.25,148.95 r0 top
L1 "SRN6045-8R2Y" IND_BOURNS_SRN6045 160.5,149.091 r90 top value=8.2uH
L2 "7443556260" WE-HCI_1890 115.85,95.25 r90 top value=2.6µH
L3 "IHLP6767GZER3R3M01" FP-IHLP-6767GZ-FP_3_825x1-MFG 59.5,124.75 r270 top value=3.3uH
P1 "S2B-PH-K-S(LF)(SN)" JST-S2B-PH-K-S_V 185,136.5 r90 top
P2 "61300511121" 61300511121 163.25,118.75 r180 top
Q1 "CSD18512Q5B" FP-DNK0008A-MFG 102.5,82.25 r180 top
Q2 "CSD18512Q5B" FP-DNK0008A-MFG 108.932,81.291 r90 top
Q3 "CSD18512Q5B" FP-DNK0008A-MFG 48.115,138.57 r90 top
Q4 "CSD18512Q5B" FP-DNK0008A-MFG 46.791,132.317 r0 top
R1 "RMCF0603ZT0R00" FP-RMCF0603-IPC_A 152.75,150.551 r270 top value=0
R2 "AC0603FR-07130RL" FP-AC0603-MFG 176,149.25 r0 top value=130
R3 "ERJ-3EKF1403V" RESC1608X55X30LL15T15 96.25,93.125 r90 bottom value=140k
R4 "RMCF0603ZT0R00" FP-RMCF0603-IPC_A 102,89.75 r270 bottom value=0
R5 "CRCW060369K8FKEB" FP-CRCW0603-e3-MFG 167,157.75 r0 top value=69.8k
R6 "RMCF0603JT1K60" FP-RMCF0603-MFG 121.25,58 r270 top value=1.6k
R7 "ERA-3AEB7871V" RESC1608X55X30NL20T20 95.6,95.25 r180 bottom value=7k87
R8 "RC0603FR-0733K2L" RESC1608X55X25ML10T15 95.5,97 r0 bottom value=33.2k
R9 "RMCF0603FT22K1" FP-RMCF0603-MFG 164.75,156 r270 top value=22k1
R10 "RC0603FR-0720KL" FP-RC0603-0_55-IPC_C 105.25,99.5 r180 bottom value=20k
R11 "RC0603FR-0720KL" FP-RC0603-0_55-IPC_C 166,128.75 r0 top value=20k
R12 "RMCF0603FT22K1" FP-RMCF0603-MFG 102.5,101.25 r180 bottom value=22k1
R13 "ERJ-3EKF1650V" RESC1608X55X30LL15T15 103.25,103.75 r90 bottom value=165
R14 "CRCW06032R10FKEA" FP-CRCW0603-e3-MFG 98,91.5 r90 bottom value=2R1
R15 "RC0603FR-07374RL" RESC1608X55X25LL10T15 107,93 r270 bottom value=374
R16 "RT0603DRD074K99L" FP-RT0603-IPC_C 99,103.25 r0 bottom value=4k99
R17 "CRCW06031K02FKEA" RESC1609X50X30LL10T20 102.5,99.5 r180 bottom value=1.02k
R18 "ERJ-3EKF1403V" RESC1608X55X30LL15T15 59.25,145 r0 bottom value=140k
R19 "RMCF0603ZT0R00" FP-RMCF0603-IPC_A 55.5,139.5 r180 bottom value=0
R20 "RT0603BRE071KL" RESC1608X55X25ML10T15 24.5,115.25 r180 top value=1k
R21 "ERA-3AEB7871V" RESC1608X55X30NL20T20 61,145.75 r90 bottom value=7k87
R22 "RC0603FR-0733K2L" RESC1608X55X25ML10T15 62.75,146 r270 bottom value=33.2k
R23 "RC0603FR-0720KL" FP-RC0603-0_55-IPC_C 65,136 r90 bottom value=20k
R24 "RC0603FR-0720KL" FP-RC0603-0_55-IPC_C 157,134 r180 top value=20k
R25 "RMCF0603FT22K1" FP-RMCF0603-MFG 67.25,138.475 r90 bottom value=22k1
R26 "RC0603FR-07158RL" RESC1608X55X25LL10T15 69.75,137.75 r180 bottom value=158
R27 "CRCW06037K15FKEAHP" FP-CRCW0603-HPe3-MFG 69.25,142.25 r270 bottom value=7k15
R28 "RC0603FR-07374RL" RESC1608X55X25LL10T15 59.5,134.75 r180 bottom value=374
R29 "CRCW06032R10FKEA" FP-CRCW0603-e3-MFG 57.25,143.5 r0 bottom value=2R1
R30 "CRCW06031K58FKEA" RESC1609X50X30LL10T20 65.5,138.575 r90 bottom value=1.58k
R31 "RMCF0603JT1K60" FP-RMCF0603-MFG 155,110.5 r0 top value=1.6k
R32 "RMCF0603JT1K60" FP-RMCF0603-MFG 154.975,91.25 r0 top value=1.6k
R33 "RMCF0603JT1K60" FP-RMCF0603-MFG 117,30.25 r270 top value=1.6k
R34 "RMCF0603JT1K60" FP-RMCF0603-MFG 136.25,30.225 r270 top value=1.6k
R35 "RMCF0603JT1K60" FP-RMCF0603-MFG 155.025,33.5 r0 top value=1.6k
R36 "RMCF0603JT1K60" FP-RMCF0603-MFG 155.025,52.5 r0 top value=1.6k
R37 "RMCF0603JT1K60" FP-RMCF0603-MFG 155,72 r0 top value=1.6k
R38 "RT0603BRE071KL" RESC1608X55X25ML10T15 30,44.5 r180 top value=1k
R39 "RT0603BRE071KL" RESC1608X55X25ML10T15 30,63.75 r180 top value=1k
R40 "RT0603BRE071KL" RESC1608X55X25ML10T15 30,101.75 r180 top value=1k
R41 "RT0603BRE071KL" RESC1608X55X25ML10T15 29.75,82.5 r180 top value=1k
R42 "RT0603BRE071KL" RESC1608X55X25ML10T15 30,25.25 r180 top value=1k
R43 "RT0603BRE071KL" RESC1608X55X25ML10T15 51.75,30.5 r270 top value=1k
R44 "RT0603BRE071KL" RESC1608X55X25ML10T15 71,30.5 r270 top value=1k
R45 "RT0603BRE071KL" RESC1608X55X25ML10T15 90.25,30.25 r270 top value=1k
R46 "CRGCQ0603J220R" FP-CRGCQ0603-IPC_C 173,133.75 r0 top value=220
R47 "RC0603FR-0710KL" FP-RC0603-0_55-MFG 129.5,100.125 r180 top value=10k
R48 "RC0603JR-076K2L" RESC1608X55X25LL10T15 68,113.75 r180 top value=6.2k
R49 "ERJ-3EKF2001V" RESC1608X55X30LL15T15 130.25,102.125 r270 top value=2k
R50 "ERJ-3EKF2001V" RESC1608X55X30LL15T15 69.75,114.375 r270 top value=2k
R51 "RMCF0603ZT0R00" FP-RMCF0603-IPC_A 133,74.949 r90 top value=0
R52 "RMCF0603ZT0R00" FP-RMCF0603-IPC_A 72.25,107 r270 top value=0
R53 "RC0603FR-0710KL" FP-RC0603-0_55-MFG 151.25,142.25 r90 top value=10k
R54 "RC0402FR-07150RL" RESC1005X40X25LL05T10 158.5,132.5 r0 top value=150
R55 "RC0402FR-07150RL" RESC1005X40X25LL05T10 158.5,138.25 r0 top value=150
R56 "RC0402FR-07150RL" RESC1005X40X25LL05T10 163.65,127 r90 top value=150
R57 "RC0402FR-07150RL" RESC1005X40X25LL05T10 157.75,135.625 r90 top value=150
SW1 "SDA01H1SBD" FP-SDA01H1SBD-MFG 5,134.371 r0 top
SW2 "SDA01H1SBD" FP-SDA01H1SBD-MFG 13.75,134.371 r0 top
SW3 "8-1437565-1" FP-8-1437565-1-MFG 147,138 r90 top
U1 "LMR54410DBVR" SOT-23-6-DBV_TEX 161.635,154.5 r180 top
U2 "LM5145RGYT" RGY0020B 102.5,95.5 r270 bottom
U3 "LM5145RGYT" RGY0020B 61.25,138.5 r180 bottom
U4 "SDT30B100D1-13" TO252_DIO 171,106.638 r180 top
U5 "SDT30B100D1-13" TO252_DIO 171,87.75 r180 top
U6 "SDT30B100D1-13" TO252_DIO 112.888,14.5 r90 top
U7 "SDT30B100D1-13" TO252_DIO 132,14.5 r90 top
U8 "SDT30B100D1-13" TO252_DIO 171,29.5 r180 top
U9 "SDT30B100D1-13" TO252_DIO 171,48.888 r180 top
U10 "SDT30B100D1-13" TO252_DIO 171,68.138 r180 top
U11 "SDT30B100D1-13" TO252_DIO 14,48 r0 top
U12 "SDT30B100D1-13" TO252_DIO 14,67.75 r0 top
U13 "SDT30B100D1-13" TO252_DIO 14,105.75 r0 top
U14 "SDT30B100D1-13" TO252_DIO 14,86.5 r0 top
U15 "SDT30B100D1-13" TO252_DIO 14,29.112 r0 top
U16 "SDT30B100D1-13" TO252_DIO 47.5,14.5 r90 top
U17 "SDT30B100D1-13" TO252_DIO 66.75,14.5 r90 top
U18 "SDT30B100D1-13" TO252_DIO 86.138,14.5 r90 top
U19 "STM32G030K8T6" FP-LQFP32-5V-MFG 166.5,135 r270 top
U20 "TMCS1108A1BQDRQ1" SOIC8_D_TEX 133.615,67.474 r90 top
U21 "TMCS1108A1BQDRQ1" SOIC8_D_TEX 67.25,107.75 r0 top

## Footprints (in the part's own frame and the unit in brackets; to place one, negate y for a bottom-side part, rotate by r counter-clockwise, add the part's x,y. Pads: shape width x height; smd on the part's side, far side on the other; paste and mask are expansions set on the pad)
61300511121 [mm] "Pin Header, pitch 2.54 mm, THT, Vertical, single row, 5p"
  rrect50% 1.6x1.6 hole 1.1: 1(-5.08,0)
  round 1.6 hole 1.1: 2(-2.54,0) 3(0,0) 4(2.54,0) 5(5.08,0)
  silkscreen extent -7.07,-1.35 6.5,1.35, body extent -6.35,-1.27 6.35,1.27, height 8.57
AMASS_XT30PW-F [mm]
  round 2.55 hole 1.7: N(-2.5,-5)
  rect 2.55x2.55 / inner round 2.55 / far side rect 2.55x2.55 hole 1.7: P(2.5,-5)
  round 1.508 hole 1: S1(5.5,0) S2(-5.5,0)
  silkscreen extent -6.65,-7.75 6.65,8.9, body extent -6.65,-6 6.65,8.9, height 5
CAPC1608X90X35LL15T15 [mm] "Chip Capacitor, 2-Leads, Body 1.60x0.81mm, IPC High Density"
  rect 0.85x0.9 smd: 1(-0.65,0) 2(0.65,0)
  body extent -0.88,-0.48 0.87,0.48, height 0.9
CONN16_S93515_WRE [mil]
  round 91 hole 71 paste-99999 mask+0: 1(0,0) 2(0,-110.24) 3(0,-220.48) 4(0,-330.72) 5(0,-440.96) 6(110.24,-440.96) 7(220.47,-440.96) 8(330.71,-440.96) 9(440.94,-440.96) 10(440.94,-330.72) 11(440.94,-220.48) 12(440.94,-110.24) 13(440.94,0) 14(330.71,0) 15(220.47,0) 16(110.24,0)
  silkscreen extent -68,-10 -65,10, body extent -28,-463 471,25, height 591
FP-8-1437565-1-MFG [mm]
  rect 1.7x1 smd paste+0 mask+0: 1(-3.15,1.9) 2(3.15,1.9) 3(-3.15,-1.9) 4(3.15,-1.9)
  silkscreen extent -4.67,-2.6 2.55,2.6, body extent -4.1,-2.7 4.1,2.7, height 0.25
FP-0603-L_1_6_0_15-W_0_81-IPC_C [mm]
  rect 0.807x0.868 smd paste+0 mask+0: 1(-0.626,0) 2(0.626,0)
  silkscreen extent -1.03,-0.88 1.03,0.88, body extent -0.8,-0.41 0.8,0.41, height 0.9
FP-1210-L_3_3_0_4-W_2_5_0-IPC_A [mm]
  rect 1.703x2.904 smd paste+0 mask+0: 1(-1.55,0) 2(1.55,0)
  silkscreen extent -0.4,-1.45 0.4,1.45, body extent -2.9,-1.95 2.9,1.95, height 0.25
FP-AC0603-MFG [mm]
  rect 0.9x0.8 smd paste+0 mask+0: 1(-0.85,0) 2(0.85,0)
  silkscreen extent -0.85,-0.82 0.85,0.82, body extent -1.4,-0.55 1.4,0.55, height 0.25
FP-C0603C-CF-IPC_B [mm]
  rect 1.007x0.958 smd paste+0 mask+0: 1(-0.726,0) 2(0.726,0)
  silkscreen extent -1.23,-0.88 1.23,0.88, body extent -0.8,-0.4 0.8,0.4, height 0.87
FP-C0603C-CF-MFG [mm]
  rect 0.75x0.9 smd paste+0 mask+0: 1(-0.6,0) 2(0.6,0)
  silkscreen extent -0.87,-0.85 0.88,0.85, body extent -0.8,-0.4 0.8,0.4, height 0.87
FP-CC0603-DA-IPC_B [mm]
  rect 1.058x0.912 smd paste+0 mask+0: 1(-0.677,0) 2(0.677,0)
  silkscreen extent -1.21,-0.86 1.21,0.86, body extent -0.8,-0.4 0.8,0.4, height 0.9
FP-CGA3E-0_3-0_1-MFG [mm]
  rect 0.7x0.7 smd paste+0 mask+0: 1(-0.7,0) 2(0.7,0)
  silkscreen extent -0.95,-0.72 0.95,0.72, body extent -1.15,-0.65 1.15,0.65, height 0.25
FP-CL830-IPC_C [mm]
  rect 0.515x0.472 smd paste+0 mask+0: 1(-0.379,0) 2(0.379,0)
  silkscreen extent -0.64,-0.67 0.64,0.67, body extent -0.74,-0.38 0.74,0.38, height 0.25
FP-CRCW0603-e3-MFG [mm]
  rect 0.75x1 smd paste+0 mask+0: 1(-0.75,0) 2(0.75,0)
  silkscreen extent -0.8,-0.9 0.8,0.9, body extent -1.22,-0.6 1.22,0.6, height 0.25
FP-CRCW0603-HPe3-MFG [mm]
  rect 0.75x1 smd paste+0 mask+0: 1(-0.75,0) 2(0.75,0)
  silkscreen extent -0.8,-0.9 0.8,0.9, body extent -0.8,-0.43 0.8,0.43, height 0.55
FP-CRGCQ0603-IPC_C [mm]
  rect 0.758x0.812 smd paste+0 mask+0: 1(-0.627,0) 2(0.627,0)
  silkscreen extent -1.01,-0.85 1.01,0.85, body extent -1.11,-0.55 1.11,0.55, height 0.25
FP-DNK0008A-MFG [mm]
  rect 1.372x0.71 smd paste-1000 mask+0: 1(-2.77,1.905) 2(-2.77,0.635) 3(-2.77,-0.635) 4(-2.77,-1.905)
  round 3.434 smd paste-1000 mask+0: 5-6-7-8(0.958,-0.317)
  Top Layer region: -0.984,-2.26 3.456,-2.26 3.456,-1.55 2.866,-1.55 2.866,-0.99 3.456,-0.99 3.456,-0.28 2.866,-0.28 2.866,0.28 3.456,0.28 3.456,0.99 2.866,0.99 2.866,1.55 3.456,1.55 3.456,2.26 -0.984,2.26
  silkscreen extent -4.23,-2.65 2.95,2.65, body extent -3.56,-2.65 3.56,2.65, height 0.25
FP-GCJ188-0_2-MFG [mm]
  rect 0.65x0.7 smd paste+0 mask+0: 1(-0.675,0) 2(0.675,0)
  silkscreen extent -0.9,-0.79 0.9,0.77, body extent -0.8,-0.4 0.8,0.4, height 0.9
FP-GCM188-0_1-MFG [mm]
  rect 0.65x0.7 smd paste+0 mask+0: 1(-0.675,0) 2(0.675,0)
  silkscreen extent -0.85,-0.75 0.85,0.75, body extent -0.8,-0.4 0.8,0.4, height 0.9
FP-GRM32-MFG [mm]
  rect 1.1x2.05 smd paste+0 mask+0: 1(-1.65,0) 2(1.65,0)
  silkscreen extent -0.72,-1.35 0.72,1.35, body extent -2.3,-1.45 2.3,1.45, height 0.25
FP-GRM155-0_05-MFG [mm]
  rect 0.4x0.5 smd paste+0 mask+0: 1(-0.4,0) 2(0.4,0)
  silkscreen extent -0.5,-0.65 0.5,0.65, body extent -0.7,-0.38 0.7,0.38, height 0.25
FP-GRM188-0_1-e0_2_0_5-IPC_B [mm]
  rect 0.959x0.912 smd paste+0 mask+0: 1(-0.727,0) 2(0.727,0)
  silkscreen extent -1.21,-0.86 1.21,0.86, body extent -0.8,-0.4 0.8,0.4, height 0.9
FP-GRM188-0_15-MFG [mm]
  rect 0.75x0.9 smd paste+0 mask+0: 1(-0.775,0) 2(0.775,0)
  silkscreen extent -0.8,-0.8 0.8,0.8, body extent -1.25,-0.58 1.25,0.58, height 0.25
FP-IHLP-6767GZ-FP_3_825x1-MFG [mm]
  rect 3.825x12.32 smd paste+0 mask+0: 1(-8.117,0) 2(8.117,0)
  silkscreen extent -8.64,-8.57 8.64,8.57, body extent -10.13,-8.67 10.13,8.67, height 0.25
FP-LQFP32-5V-MFG [mm]
  rect 1.2x0.5 smd paste+0 mask+0: 1(-4.25,2.8) 2(-4.25,2) 3(-4.25,1.2) 4(-4.25,0.4) 5(-4.25,-0.4) 6(-4.25,-1.2) 7(-4.25,-2) 8(-4.25,-2.8) 17(4.25,-2.8) 18(4.25,-2) 19(4.25,-1.2) 20(4.25,-0.4) 21(4.25,0.4) 22(4.25,1.2) 23(4.25,2) 24(4.25,2.8)
  rect 0.5x1.2 smd paste+0 mask+0: 9(-2.8,-4.25) 10(-2,-4.25) 11(-1.2,-4.25) 12(-0.4,-4.25) 13(0.4,-4.25) 14(1.2,-4.25) 15(2,-4.25) 16(2.8,-4.25) 25(2.8,4.25) 26(2,4.25) 27(1.2,4.25) 28(0.4,4.25) 29(-0.4,4.25) 30(-1.2,4.25) 31(-2,4.25) 32(-2.8,4.25)
  silkscreen extent -5.57,-3.6 3.6,3.6, body extent -4.95,-4.95 4.95,4.95, height 0.25
FP-LTST-C191KGKT-MFG [mm]
  rect 0.8x0.8 smd paste+0 mask+0: 1(-0.75,0) 2(0.75,0)
  silkscreen extent -1.85,-0.8 0.8,0.8, body extent -1.25,-0.55 1.25,0.55, height 0.25
FP-RC0603-0_55-IPC_C [mm]
  rect 0.659x0.812 smd paste+0 mask+0: 1(-0.677,0) 2(0.677,0)
  silkscreen extent -1.01,-0.85 1.01,0.85, body extent -0.8,-0.4 0.8,0.4, height 0.55
FP-RC0603-0_55-MFG [mm]
  rect 0.9x0.8 smd paste+0 mask+0: 1(-0.85,0) 2(0.85,0)
  silkscreen extent 0,-0.45 0,0.45, body extent -1.4,-0.55 1.4,0.55, height 0.25
FP-RMCF0603-IPC_A [mm]
  rect 1.206x1.058 smd paste+0 mask+0: 1(-0.801,0) 2(0.801,0)
  silkscreen extent -1.4,-0.93 1.4,0.93, body extent -1.9,-1.03 1.9,1.03, height 0.25
FP-RMCF0603-MFG [mm]
  rect 0.65x0.9 smd paste+0 mask+0: 1(-0.725,0) 2(0.725,0)
  silkscreen extent -0.85,-0.88 0.85,0.88, body extent -0.77,-0.4 0.77,0.4, height 0.55
FP-RT0603-IPC_C [mm]
  rect 0.659x0.812 smd paste+0 mask+0: 1(-0.677,0) 2(0.677,0)
  silkscreen extent -1.01,-0.85 1.01,0.85, body extent -0.76,-0.4 0.84,0.4, height 0.58
FP-S2761-46R-MFG [mm]
  rect 1.8x1 smd paste+0 mask+0: 1(0,0)
  silkscreen extent -0.85,-0.87 0.85,0.87, body extent -1,-0.6 1,0.6, height 0.25
FP-SDA01H1SBD-MFG [mil]
  rect 59x84.5 smd paste+0 mask+0: 1(0,-162.25) 2(0,162.25)
  silkscreen extent -89,-235 89,148, body extent -93,-208 93,208, height 10
FUSE_3555-2 [mm]
  round 5.59 hole 4.09: 1_1(-14.685,0) 1_2(-6.355,0) 2_1(6.345,0) 2_2(14.675,0)
  silkscreen extent -17.91,-3.3 17.91,2.25, body extent -18.03,-2.92 17.78,2.92, height 12.97
FUSE_3557-2 [mm]
  round 2.4 hole 1.6: 1_1(-6.735,1.7) 1_2(-6.735,-1.7) 2_1(6.735,1.7) 2_2(6.735,-1.7)
  silkscreen extent -9.9,-3.36 9.9,3.36, body extent -9.9,-3.36 9.9,3.36, height 7.37
IND_BOURNS_SRN6045 [mil]
  rect 79x236 smd paste+0 mask+0: 1(-85,0) 2(85,0)
  silkscreen extent -36,-127 36,127, body extent -118,-118 118,118, height 177
JST-S2B-PH-K-S_V [mm] "THD, 2-Leads, Body 7.6x5.9mm, Pitch 2mm"
  rect 1.2x1.2 hole 0.7: 1(-1,2.45)
  round 1.2 hole 0.7: 2(1,2.45)
  silkscreen extent -2.95,-3.8 2.95,4.35, body extent -2.95,-3.8 2.95,3.8, height 4.8
RESC1005X40X25LL05T10 [mm] "Chip Resistor, 2-Leads, Body 1.00x0.50mm, IPC High Density"
  rect 0.5x0.45 smd: 1(-0.375,0) 2(0.375,0)
  body extent -0.53,-0.27 0.53,0.28, height 0.4
RESC1608X55X25LL10T15 [mm] "Chip Resistor, 2-Leads, Body 1.60x0.80mm, IPC High Density"
  rect 0.6x0.8 smd: 1(-0.65,0) 2(0.65,0)
  body extent -0.85,-0.45 0.85,0.45, height 0.55
RESC1608X55X25ML10T15 [mm] "Chip Resistor, 2-Leads, Body 1.70x0.90mm, IPC Low Density"
  rect 0.8x1 smd: 1(-0.75,0) 2(0.75,0)
  body extent -0.85,-0.45 0.85,0.45, height 0.55
RESC1608X55X30LL15T15 [mm] "Chip Resistor, 2-Leads, Body 1.60x0.80mm, IPC High Density"
  rect 0.7x0.85 smd: 1(-0.625,0) 2(0.625,0)
  body extent -0.87,-0.48 0.87,0.48, height 0.55
RESC1608X55X30NL20T20 [mm] "Chip Resistor, 2-Leads, Body 1.60x0.80mm, IPC Medium Density"
  rect 0.9x1 smd: 1(-0.65,0) 2(0.65,0)
  body extent -0.9,-0.5 0.9,0.5, height 0.55
RESC1609X50X30LL10T20 [mm] "Chip Resistor, 2-Leads, Body 1.55x0.85mm, IPC High Density"
  rect 0.7x0.85 smd: 1(-0.575,0) 2(0.575,0)
  body extent -0.82,-0.48 0.82,0.48, height 0.5
RGY0020B [mm]
  rect 0.24x0.6 smd paste+0 mask+0.051: 1(-0.75,2.15) 10(-0.75,-2.15) 11(0.75,-2.15) 20(0.75,2.15)
  rect 0.6x0.24 smd paste+0 mask+0.051: 2(-1.65,1.75) 3(-1.65,1.25) 4(-1.65,0.75) 5(-1.65,0.25) 6(-1.65,-0.25) 7(-1.65,-0.75) 8(-1.65,-1.25) 9(-1.65,-1.75) 12(1.65,-1.75) 13(1.65,-1.25) 14(1.65,-0.75) 15(1.65,-0.25) 16(1.65,0.25) 17(1.65,0.75) 18(1.65,1.25) 19(1.65,1.75)
  rect 1.7x2.7 smd paste-1.337 mask+0.051: 21(0,0)
  silkscreen extent -1.95,-2.45 1.95,2.45, body extent -1.75,-2.24 1.75,2.26, height 1
SOIC8_D_TEX [mil]
  rect 57.5x22 smd paste+0 mask+0: 1(-107.25,75) 2(-107.25,25) 3(-107.25,-25) 4(-107.25,-75) 5(107.25,-75) 6(107.25,-25) 7(107.25,25) 8(107.25,75)
  silkscreen extent -84,-104 84,104, body extent -122,-99 122,99, height 69
SOT-23-6-DBV_TEX [mil]
  rect 38.5x22 smd paste+0 mask+0: 1(-53.75,37.4) 2(-53.75,0) 3(-53.75,-37.4) 4(53.75,-37.4) 5(53.75,0) 6(53.75,37.4)
  silkscreen extent -40,-65 40,65, body extent -59,-60 59,60, height 57
TAYO-C1210-2_M [mm] "Chip Capacitor, 2-Leads, Body 3.50x2.70mm, IPC Low Density"
  rect 1.75x2.8 smd: 1(-1.425,0) 2(1.425,0)
  silkscreen extent -0.15,-1.3 0.15,1.3, body extent -1.75,-1.35 1.75,1.35, height 2.7
TO252_DIO [mil]
  rect 27x69 smd paste+0 mask+0: 1(-90,-207.93) 2(90,-207.93)
  rect 217x237 smd paste+0 mask+0: 3(0,64.5)
  silkscreen extent -135,-159 135,125, body extent -130,-228 130,169, height 91
WE-HCI_1890 [mm] "SMT Flat Wire High Current Inductor, body 18.2x18.2mm"
  rect 6x6 smd: 1(0,6.65) 2(0,-6.65)
  silkscreen extent -9.35,-9.35 9.35,9.35, body extent -9.1,-9.15 9.1,9.15, height 8.9
WL-SMCW_1206_150120xx75000 [mm] "SMD Mono-color Chip LED, body 3.2x1.6mm"
  rect 1.4x1.6 smd: 1(-1.5,0) 2(1.5,0)
  silkscreen extent -2.6,-0.75 -2.4,0.75, body extent -1.6,-0.8 1.6,0.8, height 0.68

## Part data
C1 C2 C5 C24 C25 C28 C47 C48: library part CMP-001-00163-1, "CGA Series 0603 0.1 uF 50 V ±10% Tolerance X8R Multilayer Ceramic Capacitor", Case/Package=0603, Max Operating Temperature=150°C, Min Operating Temperature=-55°C, Tolerance=10%, Voltage Rating=50V
C3 C4 C19 C20 C21 C22 C23 C42 C43 C44 C45 C46: library part CMP-001-00137-1, "Ceramic Capacitor, Multilayer, Ceramic, 50V, 10% +Tol, 10% -Tol, X7R, 15% TC, 4.7uF, Surface Mount, 1210", Capacitor Type=Ceramic, Case/Package=1210, Max Operating Temperature=125°C, Min Operating Temperature=-55°C
C6: library part CMP-001-00183-1, "50V 10uF X5R ±20% 1210 Multilayer Ceramic Capacitors MLCC - SMD/SMT ROHS", Case/Package=1210, Max Operating Temperature=85°C, Min Operating Temperature=-55°C, Tolerance=20%, Voltage Rating=50V
C7 C8 C9 C10 C11 C12 C13 C14 C29 C30 C31 C32 C33 C34 C35: library part CMP-001-00168-1, "25V 22uF X5R ±10% 1210 Multilayer Ceramic Capacitors MLCC - SMD/SMT ROHS", Case/Package=1210, Max Operating Temperature=85°C, Min Operating Temperature=-55°C, Tolerance=10%, Voltage Rating=25V
C15: library part CMP-001-00170-1, "Ceramic Capacitor, YES, Ceramic, 16V, 10% +Tol, 10% -Tol, X7R, 15% TC, 0.039uF, Surface Mount, 1608M/0603", Case/Package=0603, Max Operating Temperature=125°C, Min Operating Temperature=-55°C, Tolerance=10%, Voltage Rating=16V
C16 C37: library part CMP-001-00153-1, "Ceramic Capacitor, Multilayer, Ceramic, 35V, 10% +Tol, 10% -Tol, X5R, 15% TC, 2.2uF, Surface Mount, 0603", Capacitor Type=Ceramic, Case/Package=0603, Max Operating Temperature=85°C, Min Operating Temperature=-55°C
C17 C38: library part CMP-001-00143-1, "Ceramic Capacitor, Multilayer, Ceramic, 50V, 5% +Tol, 5% -Tol, X7R, 15% TC, 0.0047uF, Surface Mount, 0603", Capacitor Type=Ceramic, Case/Package=0603, Max Operating Temperature=125°C, Min Operating Temperature=-55°C
C18: library part CMP-001-00171-1, "C0603C 820PF Ceramic Multilayer Capacitor, 50 VDC, +125DEGC, X7R Dielec, +/-10%", Case/Package=0603, Max Operating Temperature=125°C, Min Operating Temperature=-55°C, Tolerance=10%, Voltage Rating=50V
C26 C40: library part CMP-001-00146-1, "Ceramic Capacitor, Multilayer, Ceramic, 50V, 5% +Tol, 5% -Tol, C0G, 30ppm/Cel TC, 0.000015uF, Surface Mount, 0603", Capacitor Type=Ceramic, Case/Package=0603, Max Operating Temperature=125°C, Min Operating Temperature=-55°C
C27: library part CMP-001-00148-1, "Ceramic Capacitor, Multilayer, Ceramic, 50V, 10% +Tol, 10% -Tol, X7R, 15% TC, 0.00022uF, Surface Mount, 0603", Capacitor Type=Ceramic, Case/Package=0603, Max Operating Temperature=125°C, Min Operating Temperature=-55°C
C36: library part CMP-001-00182-1, "Ceramic Capacitor, YES, Ceramic, 50V, 10% +Tol, 10% -Tol, X8L, -40/+15% TC, 0.082uF, Surface Mount, 1608M/0603", Case/Package=0603, Max Operating Temperature=150°C, Min Operating Temperature=-55°C, Tolerance=10%, Voltage Rating=50V
C39: library part CMP-001-00145-1, "Ceramic Capacitor, Multilayer, Ceramic, 50V, 10% +Tol, 10% -Tol, X7R, 15% TC, 0.0012uF, Surface Mount, 0603", Capacitor Type=Ceramic, Case/Package=0603, Max Operating Temperature=125°C, Min Operating Temperature=-55°C
C41: library part CMP-001-00144-1, "Ceramic Capacitor, Multilayer, Ceramic, 50V, 5% +Tol, 5% -Tol, C0G, 30ppm/Cel TC, 0.00015uF, Surface Mount, 0603", Capacitor Type=Ceramic, Case/Package=0603, Max Operating Temperature=125°C, Min Operating Temperature=-55°C
C49: library part CMP-001-00175-1, "25V 4.7uF X5R ±10% 0603 Multilayer Ceramic Capacitors MLCC - SMD/SMT ROHS", Case/Package=0603, Max Operating Temperature=85°C, Min Operating Temperature=-55°C, Tolerance=10%, Voltage Rating=25V
C50 C51 C52: library part CMP-001-00174-1, "25V 100nF X7R 卤10% 0402 Multilayer Ceramic Capacitors MLCC - SMD/SMT ROHS", Case/Package=0402, Max Operating Temperature=125°C, Min Operating Temperature=-55°C, Tolerance=10%, Voltage Rating=25V
C53 C54 C55 C56: library part CMP-001-00142-1, "Ceramic Capacitor, Multilayer, Ceramic, 50V, 5% +Tol, 5% -Tol, C0G, 30ppm/Cel TC, 0.001uF, Surface Mount, 0402", Capacitor Type=Ceramic, Case/Package=0402, Max Operating Temperature=125°C, Min Operating Temperature=-55°C
D1 D2 D3 D4 D5 D6 D7 D8 D9 D10 D11 D12 D13 D14 D15 D16 D17 D18: library part CMP-007-00044-1, "Single Color LED, Bright Green, Water Clear, 2mm", Forward Current=30mA, Max Operating Temperature=85°C, Min Operating Temperature=-40°C
D19: library part CMP-004-00036-1, "LED yellow green 0603 wavelength 567.5~576.5nm light intensity 18~71mcd Front Mounting", Case/Package=0603, Forward Current=30mA, Forward Voltage=2.4V, Max Operating Temperature=85°C, Min Operating Temperature=-55°C
F1 F4 F5 F6 F7 F8 F9 F10 F11 F12 F13 F14 F15 F16 F17 F18: library part CMP-005-00014-1, "THM 2 in 1 Auto Blade Holder", Case/Package="Nonstandard Keystone"
F2 F3: library part CMP-005-00015-2, "Auto Fuse Holder, 1 Fuse, Blade, Standard, THM, 50Amp, Hi-Temp Nylon, UL94V-0", Case/Package=None
J1 J2 J3 J4 J5 J6 J7: library part CMP-002-00083-1, "Interconnection Device"
J8 J9 J10 J11 J12 J13 J14 J15 J16 J17 J18 J19 J20 J21 J22: library part CMP-002-00091-1, "Socket; DC supply; XT30; female; PIN: 2; on PCBs; THT; yellow; 15A", Case/Package=None
J23 J24 J25 J26: library part CMP-083-000000-2, "Description", Manufacturer_Name="Wurth Electronics"
L1: library part CMP-006-00036-1, "Description", Manufacturer_Name="Bourns Electronics"
L2: library part CMP-006-00034-1, "WE-HCI SMT Flat Wire High Current Inductor", Case/Package=1890, Current Rating=31.5A, Max Operating Temperature=150°C, Min Operating Temperature=-40°C, Self Resonant Frequency=42MHz, Tolerance=20%
L3: library part CMP-006-00032-1, "Inductor High Current Shielded Wirewound 3.3uH 20% 100KHz 28A 3.88mOhm DCR 6767 T/R", Case/Package=6767, Current Rating=28A, Max Operating Temperature=125°C, Min Operating Temperature=-55°C, Tolerance=20%
P1: library part CMP-002-00030-2, "Male Header, Pitch 2 mm, 1 x 2 Position, Height 4.8 mm, Tail Length 3.4 mm, -25 to 85 degC, RoHS, Bulk", Case/Package=S2B-PH-K-S, Manufacturer="Japan Solderless Terminals", Max Operating Temperature=85°C, Min Operating Temperature=-25°C, Package Description="Male Header, Pitch 2 mm, 1 x 2 Position, Height 4.8 mm, Tail Length 3.4 mm"
P2: library part CMP-002-00093-1, "WR-PHD Straight Male, PCB Header, Through Hole, 1 Rows, 5 Contacts, 2.54mm Pitch", Max Operating Temperature=105°C, Min Operating Temperature=-40°C, Voltage Rating=250V
Q1 Q2 Q3 Q4: library part CMP-013-00041-1, "40-V, N channel NexFET™ power MOSFET, single SON 5 mm x 6 mm, 1.6 mOhm 8-VSON-CLIP -55 to 150", Max Operating Temperature=150°C, Min Operating Temperature=-55°C
R1 R4 R19 R51 R52: library part CMP-009-00236-1, "Fixed Resistor, Metal Glaze/thick Film, 0.1W, 0ohm, Surface Mount, 0603", Case/Package=0603, Max Operating Temperature=155°C, Min Operating Temperature=-55°C, Power=100mW
R2: library part CMP-009-00292-1, "Res Thick Film 0603 130 Ohm 1% 0.1W(1/10W) ±100ppm/C Pad SMD T/R Automotive AEC-Q200", Case/Package=0603, Max Operating Temperature=155°C, Min Operating Temperature=-55°C, Tolerance=1%, Voltage Rating=75V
